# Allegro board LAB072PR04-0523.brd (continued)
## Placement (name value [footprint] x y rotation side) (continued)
T4928  PAD~D  [TPC12]  186.71 48.77 180 top
T4929  PAD~D  [TPC12]  185.77 49.77 180 top
T4930  PAD~D  [TPC12]  183.75 106.91 180 bottom
T4931  PAD~D  [TPC12]  152.21 98.78 0 top
T4932  PAD  [TPC12]  154.33 22.65 0 top
T4933  PAD  [TPC12]  154.2 85.73 0 top
T4934  PAD  [TPC12]  152.32 89.09 0 top
T4935  PAD  [TPC12]  153.18 88.13 0 top
T4939  PAD  [TPC12]  156.34 92.22 0 top
TL2  TAIMA_IH-115-F  [TAIMA_IH-115-F_24P]  187.84 80.38 90 bottom
U2301  -  [TPS22966DPUR_SON14_2X3]  179.07 52.27 0 top
U2302  -  [W25Q64FVSSIQ_SO8]  172.13 104.96 90 bottom
U2303  -  [74AUP1G07GW_TSSOP5]  134.92 58.62 270 top
U2304  -  [TPS22966DPUR_SON14_2X3]  179.99 63.37 90 top
U2412  ECE1117-HZH_QFN48_7X7~D  [ECE1117-HZH_QFN48_7X7]  82.36 13.48 0 top
UA1  -  [ALC3234-CG_MQFN48_6X6]  183.57 22.02 270 top
UC1  HASWELL-MCP-E-ULT_BGA1168  [HASWELL-MCP-E-ULT_BGA_1168P-T]  156.14 104.99 0 bottom
UC3  -  [MC74VHC1G08DFT2G_SC70-5]  176.92 84.95 180 top
UC4  -  [74CBTLV3126BQ_DHVQFN14_2P5X3]  88.52 89.92 90 top
UC5  -  [74AHC1G09GW_TSSOP5]  174.11 108.05 90 top
UC6  -  [74AUP1G07GW_TSSOP5]  124.39 113.08 180 top
UE4  ECE1099-FZG_QFN40_6X6~D  [ECE1099-FZG_QFN40_6X6]  94.62 19.58 270 top
UE5  -  [MEC5085-LZY_DQFN132_11X11]  146.55 9.72 0 top
UI2  -  [SY6288D20AAC_SOT23-5]  194.3 27.1 0 top
UI3  -  [SY6288D20AAC_SOT23-5]  195.25 35.86 90 top
UI4  -  [SY6288D20AAC_SOT23-5]  21.84 39.68 0 top
UL1  RTL8111GUS-CG_QFN32_4X4  [RTL8106E-CG_QFN32_4X4]  182.71 88.33 270 bottom
UL2  -  [SY6288C20AAC_SOT23-5]  182.69 82.73 270 top
UM1  -  [TPS22967DSGR_SON8_2X2]  176.35 50.87 90 top
US2  -  [PI3EQX6741STZDEX_TQFN20_4X4]  168.37 21.88 270 top
UV1  GM108-ES-S-A1_FCBGA595  [GM108-ES-S-A1_FCBGA_595P]  74.76 97.37 180 bottom
UV3  74AHCT1G125GW_SOT353-5~D  [74AHCT1G125GW_SOT353-5]  197.54 109.26 90 bottom
UV4  -  [AP2330W-7_SC59-3]  199.77 112.96 270 bottom
UV5  74AHCT1G125GW_SOT353-5~D  [74AHCT1G125GW_SOT353-5]  195.38 112.75 90 bottom
UV6  -  [IT6513FN_QFN48_6X6]  191.13 109.89 270 bottom
UV14  -  [MC74VHC1G08DFT2G_SC70-5]  79.75 82.97 90 top
UV15  -  [TPS22966DPUR_SON14_2X3]  87.82 102.73 270 bottom
UV17  H5TC4G63AFR-11C_FBGA96  [H5TC4G63AFR-11C_FBGA_96P]  43.01 95.15 90 bottom
UV18  H5TC4G63AFR-11C_FBGA96  [H5TC4G63AFR-11C_FBGA_96P]  43.01 101.55 270 top
UV19  H5TC4G63AFR-11C_FBGA96  [H5TC4G63AFR-11C_FBGA_96P]  43.01 81.74 270 top
UV20  H5TC4G63AFR-11C_FBGA96  [H5TC4G63AFR-11C_FBGA_96P]  43.01 75.34 90 bottom
UX1  -  [SY6288C20AAC_SOT23-5]  12.12 86.14 180 top
UX3  -  [SY6288C20AAC_SOT23-5]  14.64 100.71 0 top
YC1  32.768KHZ_12.5PF_9H03220008  [Y_9H03220008_2P]  159.29 76 180 top
YC2  24MHZ_12PF_X3G024000DC1H  [Y_X3G024000DC1H_4P]  136.79 112.65 180 bottom
YE1  32.768KHZ_9PF_Q13FC135000040  [Y_Q13FC135000040_2P]  140.01 10.19 270 top
YL2  25MHZ_10PF_7V25000014  [Y_7V25000014_4P]  184.34 94.38 180 bottom
YV1  27MHZ_12PF_X1E000021042600  [Y_X1E000021042600_4P]  75.79 106.52 0 bottom
YV3  27MHZ_12PF_X1E000021042600  [Y_X1E000021042600_4P]  182.9 113.16 180 bottom

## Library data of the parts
C7 C39-C45 C60 C66 C72 C74 C78 C82 C2305 C2306 C2308 C2309 C2311-C2318 C2322-C2325 C2328 C2329 C5259 C5261-C5263 CA55 CA57 CA59 CA61-CA64 CA67 CA68 CA71 CA74 CA77 CE4 CE42 CE45 CI40 CI43 CI44 CI49 CL43-CL45 CM4 CM6 CV15 CV16 CV24 CV32 CV33 CV36 CV39 CV42 CV43 CV46 CV47 CV65 CV112 CV130 CV135 CV136 CV158-CV160 CV164 CV340 CV361 CX5 CX22 PC103 PC106 PC312 PC313 PC520 PC525 PC528 PC605 PC614 PC617 PC625 PC700 PC723-PC725 PC745 PC751 PC752 PC924 PC925 PC928 PC930 PC938-PC941 PC952 PC953 PC1004 PC1006 = C_0603
C35-C38 C50-C58 C61-C64 C67-C69 C71 C73 C76 C77 C80 C81 C83 C85 C87 C88 C1160 C1313 C2326 C2327 C5212 C5254-C5256 C5291-C5293 CA21 CA26 CA32 CA38-CA40 CA54 CA56 CA58 CA60 CA65 CA69 CA75 CA76 CC14-CC16 CC41 CC42 CE3 CE10 CE13 CE14 CE17 CE21 CE38-CE41 CE43 CE44 CE46-CE55 CE58-CE66 CE68-CE70 CI2 CI9 CI15 CI26 CI46-CI48 CI50 CL20-CL22 CL24-CL26 CL30 CL31 CL34-CL37 CL39 CL41 CL42 CM3 CM5 CM7 CM8 CS5 CS6 CS27-CS29 CV30 CV34 CV35 CV40 CV45 CV48-CV64 CV68 CV129 CV131-CV134 CV139-CV143 CV151 CV161 CV163 CV165 CV168 CV170 CV172-CV174 CV178-CV181 CV183 CV184 CV186 CV187 CV196-CV199 CV203-CV205 CV208-CV211 CV215-CV218 CV326 CV334-CV339 CV341 CV343-CV345 CV351-CV360 CX2 CX4 CX6 CX10-CX21 CX23-CX31 CX50 CZ49-CZ51 PC2 PC3 PC9-PC11 PC16 PC17 PC104 PC108 PC202 PC210 PC521-PC523 PC526 PC527 PC529-PC531 PC541 PC545 PC546 PC548 PC600-PC602 PC606-PC608 PC612 PC615 PC616 PC618 PC619 PC622 PC626 PC746 PC747 PC750 PC926 PC927 PC929 PC931 PC1000 PC1001 PC1005 PC1009 = C_0402
C59 C65 C70 C84 C86 CL33 = C_1206
C2307 C2310 CS7 CX3 CX7 CX8 CX49 CX51 PC18 PC112 PC206 PC311 PC524 PC532 PC603 PC604 PC620 PC621 PC627 PC730-PC732 PC734 PC748 PC905-PC912 PC918-PC921 PC932-PC937 PC942 PC949-PC951 PC1002 PC1003 = C_0805
C4311-C4314 C4321 C4322 CM1 CM2 CS30-CS37 CV342 CV346-CV350 = C_0402: signal model: C_0402_C_0402
CA22-CA25 CA29-CA31 CA33 CA51 = C_0402: room: CODEC
CA53 = C_0603: room: CODEC
CC1-CC5 CC8 CC11 CC13 CC17 CC27-CC29 CC31 CC33-CC35 PC207 = C_0402: room: CPU
CC6 CC7 CC9 CC10 = C_0402: room: SPI
CC18-CC25 CV188-CV195 = C_0402: signal model: C_0402_0.22U_0402_16V7K
CC26 = C_0603: room: CPU
CC32 CC40 = C_0402: signal model: C_0402_C_0402; room: CPU
CD1-CD11 CD21-CD27 CD30-CD42 CD52-CD57 CD60 CD61 CD64 = C_0402: room: MEMORY
CD12-CD14 CD16-CD20 CD28 CD29 CD43-CD50 CD58 CD59 CD62 = C_0603: room: MEMORY
CD15 CD51 = C_D3: room: MEMORY
CE24 = C_0402: room: KBC
CI1 CI8 = C_1206: room: USB
CI3 CI4 CI10 CI11 CI13 CI17 = C_0402: room: USB
CI6 CI12 = C_0603: room: USB
CL15 = C_0402: room: LAN
CL19 = C_0402: room: HDMI
CMOS1 = SHORTPADS: User Part Number: PART#; room: CPU
D1 = RB751S40T1G_SOD523-2
DA8 DC1 DV1 DV2 DV7 = BAT54CW_SOT323-3
DA10 DA13 DX2-DX4 = AZ5125-02SPR7G_SOT23-3
DA12 DA14 = ESD207-B1-02EL_TSLP-2-19-2
DE1 = AZ5125-02SPR7G_SOT23-3: room: FAN
DE2 PD3 = AZ5125-01HPR7G_SOD523-2
DE3 DS1 DV5 DV6 = PJDLC05C_SOT23-3
DI1 DI4 = IP4292CZ10-TBR_XSON10_2P5X1: room: USB
DI2 DI5 = PJDLC05C_SOT23-3: room: USB
DV3 = RB751V-40_SOD323-2
F1 = F_KMC3S050RY
FD1-FD4 = FIDUCIAL_C40M80
FX1 = F_1206L150THWR
H1 = H_2P3: room: LED
H2 = H_2P8X3P1N: room: LED
H3 H4 H8 H11 H17 H19 = H_2P8: room: LED
H5 = H_6P6: room: LED
H6 = H_3P5: room: LED
H7 = H_3P2X3P5: room: LED
H9 = H_3P2X3P5
H10 = H_3P2
H12 = H_2P3N: room: LED
H14 = H_6P0: room: LED
H15 = H_3P2: room: LED
H20 H21 = H_1P1N
H22-H24 = H_3P3
JBATT = ALLTO_C144LS-109A9-L_9P-T
JCRT = C-K_80443A-5K1-152_15P
JDCIN = ACES_50299-00501-003_5P
JDEG JLPDE = ACES_87153-10411_10P
JDIMM1 = FOX_AS0A621-U4R6-7H_204P: room: CPU
JDIMM2 = FOX_AS0A621-U4S6-7H_204P: room: CPU
JEDP = ACES_50398-04041-001_40P
JFAN = ACES_50279-0040N-001_4P
JFP = ACES_51524-0060N-001_6P
JHDD = ACES_50208-01001-001_10P
JHDMI = CONCR_099ATAC19NBLCNF_19P
JHP = SINGA_2SJ3080-001111F_6P
JIO = ACES_51524-0160N-001_16P
JKB = ACES_51510-0304N-P01_30P
JKBBL = ACES_50524-00401-P01_4P
JLAN = J-L_TNBNRAC80015008_8P
JLED JTP = ACES_51524-0080N-001_8P
JNGFF = LOTES_APCI0019-P009A_67P
JRTC = ACES_50271-0020N-001_2P
JSPK = ACES_50278-00401-001_4P
JTAG1 = SHORTPADS: User Part Number: PART#
JUSB1 JUSB2 = TAITW_PUBAU6-09FLBS1NN4H0_9P: room: USB
JXDP = SAMTE_BSH-030-01-L-D-A_60P
L1-L5 = MURAT_LQM2MPN2R2NG0L_2P
L12 LX6 LX7 = MURAT_DLW21HN900HQ2L_4P: signal model: KC_WCM-2012HS-900T_4P_KC_WCM-2012HS-900T_4P
L18 = CHILI_NLC252018T-2R2J-N_2P
LA1 RA1121-RA1124 = MURAT_BLM15BB221SN1D_2P
LA8 LA9 = MURAT_BLM15BB221SN1D_2P: room: CODEC
LA10 LA11 = MURAT_BLM15PX330SN1D_2P
LI1 LI3 LI4 LI6 = MURAT_DLW21SN670HQ2L_4P: room: USB
LI2 LI5 = MURAT_DLW21HN900HQ2L_4P: room: USB
LV8 = TAI-T_HCB1608KF-121T3_L0603_2P
LV10 LV26 = MURAT_BLM18PG300SN1D_2P
LV14 LV15 LV21 = MURAT_BLM15PD600SN1D_2P
LV16-LV18 = MURAT_BLM15BB470SN1D_2P
LV19 LV20 = MURAT_BLM15AG121SN1D_L0402_2P
LX1 = KC_FBMA-L11-201209-221LMA30_2P
LX2-LX5 = MURAT_DLW21HN900HQ2L_4P
LX8-LX10 = MURAT_DLW21SN670HQ2L_4P
PC1 = C_0402: room: P_DCIN
PC5 = C_0603: room: P_DCIN
PC100 PC105 PC109 PC111 PC200 PC204 PC209 PC301 PC302 = C_0603: room: ETY-ROOM
PC101 = C_APXK6R3ARA221MF451: room: ETY-ROOM
PC102 PC110 PC114 PC201 PC203 PC300 PC303 PC304 PC307 PC400 PC402 PC403 PC500 PC510 PC519 = C_0402: room: ETY-ROOM
PC107 = C_APXK6R3ARA221MF451
PC113 = C_0402: room: 3V5V
PC115 = C_0805: room: 3V5V
PC116 PC117 PC299 = C_D2-NPM
PC205 PC211 PC212 PC305 PC306 PC308-PC310 PC401 PC404 = C_0805: room: ETY-ROOM
PC208 = C_0402: room: ADP3209
PC214 = C_MP6VU330MC6
PC515 PC516 = C_EEEFZ1E101P-NPM: room: CPU_CORE
PC517 PC518 = C_0805: room: CPU_CORE
PC533 PC534 = C_D
PC610 PC613 PC623 PC1008 = C_D2
PC701-PC703 PC718 PC719 PC726-PC728 = C_0402: room: CHARGER
PC704-PC711 PC716 PC717 PC720 = C_0805: room: CHARGER
PC712 PC722 = C_0603: room: CHARGER
PC721 = C_0805: room: ADP3209
PC729 = C_0603: room: P_SELECTOR
PC901-PC904 PC913-PC917 PC922 PC923 = C_0805: room: CPU
PD1 PD2 = TVNST52302AB0_SOT523-3: room: ETY-ROOM
PD101 = TVNST52302AB0_SOT523-3
PD702 PD703 = SDMK0340L-7-F_SOD323-2
PH500 PH501 PR102 PR104-PR108 PR114 PR205 PR207 PR208 PR301 PR305 PR307 PR400-PR403 PR500 PR512 PR528 PR539 = R_0402: room: ETY-ROOM
PH600 PR3-PR5 PR9-PR11 PR13 PR110 PR115 PR204 PR304 PR309 PR310 PR525 PR533 PR537 PR543 PR545 PR549 PR551 PR558 PR600 PR602-PR604 PR607 PR608 PR610 PR611 PR614 PR615 PR617 PR620 PR621 PR624 PR706 PR729-PR732 PR737 PR739-PR741 PR1000 PR1002 PR1005-PR1007 R1 R2 R10 R11 R16 R159 R944 R990 R2313 R2318 R2329-R2345 R2347-R2353 R2356-R2359 R2363 R2484 R2495 R2517 R2518 R2521-R2528 RA10 RA19 RA53 RA55 RA56 RA79-RA84 RA130 RA165 RA166 RA1109 RA1112 RA1113 RA1120 RA1128-RA1130 RC5 RC6 RC9 RC12 RC13 RC24 RC27 RC28 RC32 RC36 RC39 RC48 RC51 RC56 RC58 RC60 RC64 RC71 RC75 RC80 RC84 RC90 RC92 RC95 RC101 RC105 RC108 RC109 RC111 RC114 RC117 RC129 RC134 RC135 RC153 RC183 RC191 RC362-RC366 RC368-RC374 RE13 RE14 RE24-RE26 RE31 RE33 RE35 RE38 RE39 RE45 RE48 RE50 RE55-RE57 RE61 RE63-RE67 RE69 RE70 RE72 RE74-RE82 RE87 RE89 RE90 RE274 RE278-RE280 RL27 RL30 RL31 RL33 RL41 RM8 RN5 RS8 RS19 RS21 RS22 RS24 RS25 RS30 RS32 RS33 RS35 RS36 RS38 RS40-RS43 RV18 RV20 RV23-RV26 RV30-RV49 RV51 RV59 RV92-RV99 RV103 RV104 RV107 RV108 RV110 RV112 RV114 RV117-RV119 RV122-RV130 RV132 RV139 RV140 RV142-RV157 RV159-RV162 RV169-RV171 RV185 RV187-RV193 RV195 RV196 RV208 RV210 RV252 RV253 RV510-RV520 RX2 RX3 RX9 RX12 RX13 RX16 RX17 RX21 RX22 RX26 RX29-RX31 = R_0402
PJP12 PJP14 PJP15 PJP30 PJP31 PJP203 PJP701 = JUMP_43X39
PJP13 PJP400 PJP401 PJP510-PJP513 = JUMP_43X79
PJP100 PJP101 PJP300 = JUMP_43X118: room: ETY-ROOM
PJP103 PJP200 PJP201 PJP1000 = JUMP_43X118
PL1 PL2 PL4 = TAI-T_HCB2012KF-121T50_2P: room: P_DCIN
PL3 = MURAT_BLM15AG102SN1D_2P: room: P_DCIN
PL5-PL8 PL103 PL201 PL302 PL504 PL600 PL603 PL1000 = TAI-T_HCB2012KF-121T50_2P
PL100 PL101 PL200 = L_7X7X3_M_2P: room: ETY-ROOM
PL102 = TAI-T_HCB2012KF-121T50_2P: room: VDDCI
PL301 = L_5X5X3_M_2P: room: ETY-ROOM
PL501 = TAI-T_HCB2012KF-121T50_2P: room: CPU_CORE
PL502 = CYNTE_PCMB104T-R15MS0R485_4P
PL601 PL602 = PANAS_ETQP3W2R2WFN_2P
PL700 = L_5X5X3_M_2P
PL701 = L_10X10X4_M_2P: room: ETY-ROOM
PL1001 = L_7X7X3_M_2P
PQ1 = FDV301N_NL_SOT23-3: room: P_DCIN
PQ2 = MMST3904-7-F_SOT323-3: room: P_DCIN
PQ3 = 2N7002KDWH_SOT363-6
PQ101 PQ103 = MDV1528URH_PDFN33-8-5: room: ETY-ROOM
PQ102 = FDMC7692S_MLP8-5: room: ETY-ROOM
PQ104 PQ201 = FDMC7692S_MLP8-5
PQ200 = MDV1528URH_PDFN33-8-5
PQ501 = CSD87351Q5D_SON8-7
PQ600 PQ602 = MDU1516URH_POWERDFN56-8-5
PQ601 PQ603 = MDU1511RH_POWERDFN56-8-5
PQ701 = MDU1516URH_POWERDFN56-8-5: room: ETY-ROOM
PQ702 = MDS1525URH_SO8: room: ETY-ROOM
PQ703 = AO4407AL_SO8
PQ704 = SIR472DP-T1-GE3_POWERPAK8-5
PQ705 = SIRA06DP-T1-GE_POWERPAKSO-8-5
PQ708 = DCX124EK-7-F_SC74R-6
PQ709 = DMN65D8LW-7_SOT323-3
PQ1000 = SIS412DN-T1-GE3_POWERPAK8-5
PQ1001 = MDV1526URH_PDFN33-8-5
PR2 PR6-PR8 = R_0402: room: P_DCIN
PR12 PR613 PR622 PR1004 = R_1206
PR16 RM7 = R_0805
PR100 PR101 PR201 PR202 = R0402_0OHM: room: ETY-ROOM
PR103 PR111 PR206 PR303 PR536 = R_0603: room: ETY-ROOM
PR109 PR519 = R_0402: room: CPU_CORE
PR112 PR113 PR203 PR302 PR534 = R_1206: room: ETY-ROOM
PR200 = R_0603: room: CPU_CORE
PR300 PR601 PR605 PR612 PR616 PR719 PR721 PR738 PR1003 R248 R250 R251 R265 R416 R2355 R2360 R2451 R2532 RC37 RC40-RC47 RC49 RC52-RC55 RC57 RC59 RC78 RC97 RC107 RC367 RD1 RD8 RE32 RE58 RE62 RE275 RM5 RM6 RS39 RV163 RV164 RV215 RX32-RX37 = R0402_0OHM
PR306 PR308 = R_0402: room: 1P5V
PR504 PR507 PR521 PR535 = R_0402: room: GPU_CORE
PR505 PR506 PR508 PR510 PR511 = R0402_0OHM: room: GPU_CORE
PR513 PR538 PR606 PR609 PR618 PR619 PR623 PR1001 R245 R2314 RL39 RL40 RX28 = R_0603
PR702 = R_1206_4P-D
PR704 PR713 PR715 PR725 = R_0402: room: CHARGER
PR705 PR714 PR716-PR718 PR720 PR728 = R0402_0OHM: room: CHARGER
PR708 PR711 = R_1206: room: CHARGER
PR710 = R_1206_4P-D: room: CHARGER
PR712 = R_0603: room: 3V5V
PR723 = R_0603: room: CHARGER
PRP1 RP37 RP39 RP40 RP43 RP44 RP48 RP51-RP53 RP55 RP58-RP60 RPE3 RPE5-RPE7 RPE9 RPE10 RPV3 = RP_0804_8P4R
PU100 = TPS51285BRUKR_QFN20_3X3: room: ETY-ROOM
PU200 = G5616ARZ1U_TQFN20_3X3: room: ETY-ROOM
PU300 = SY8206DQNC_QFN10_3X3: room: ETY-ROOM
PU400 = APL5930KAI-TRG_SO8: room: ETY-ROOM
PU501 = ISL95813HRZ-T_QFN20_3X4: room: ETY-ROOM
PU600 = RT8813AGQW_WQFN24_4X4
PU700 = BQ24777RUYR_WQFN28_4X4
PU1000 = TPS51212DSCR_SON10_3X3
Q8-Q10 Q2307 Q2416 QX3 = 2N7002K_SOT23-3
Q327 QA7 QD2 QE11 QV5 QV78 QV88 QX1 = L2N7002WT1G_SC-70-3
Q330 QX5 = AO3419L_SOT23-3
QA6 QV14 QV89 QX4 = DMN66D0LDW-7_SOT363-6
QC1 = DMN66D0LDW-7_SOT363-6: room: CPU
QE3 QE7-QE10 QE12 = MMST3904-7-F_SOT323-3
QX2 = SI3457CDV-T1-GE3_TSOP6
R246 RA1110 RA1111 RA1114-RA1117 RA1125 RV214 = R0603_0OHM
R252-R256 = R_0402: room: DOCK
R257 = R0402_0OHM: room: DOCK
R264 = R0603_0OHM: room: DOCK
R267 = R0805_0OHM: room: DOCK
RA5 RA6 = R_0402: room: CODEC
RA8 = R0402_0OHM: room: CODEC
RC1 RC2 RC4 RC7 RC8 RC10 RC14-RC23 RC25 RC34 RC63 RC65-RC70 RC72 RC87 RC89 RC91 RC98 RC102 RC103 RC106 RC116 RC118-RC121 RC130-RC133 = R_0402: room: CPU
RC29 = R_0402: room: FLASH ROM
RC38 RC50 = R0402_0OHM: room: SPI
RC62 = R_0402: room: SPI
RC81 RC127 = R0402_0OHM: room: CPU
RC126 = R0603_0OHM: room: CPU
RD3 RD6 RD7 RD12 RD13 = R_0402: room: MEMORY
RD4 RD5 RD10 = R0402_0OHM: room: MEMORY
RL19 RL20 = R_0603: room: LOM
RS26 RS27 RX23 RX24 = R_0402: signal model: R_0402_R_0402
SW1 = SW_SMT1-05-A_4P: room: CPU
SW3 = SW_SSAL120100_3P
T27 T32 T38-T51 T53 T55 T56 T58 T59 T87 T94-T96 T99-T102 T110-T121 T124 T126-T159 T161 T163-T177 T179-T184 T3861 T3862 T4927-T4935 T4939 = TPC12
T97 T98 = TPC12: room: SIO
TL2 = TAIMA_IH-115-F_24P
U2301 U2304 UV15 = TPS22966DPUR_SON14_2X3
U2302 = W25Q64FVSSIQ_SO8
U2303 UC6 = 74AUP1G07GW_TSSOP5
U2412 = ECE1117-HZH_QFN48_7X7
UA1 = ALC3234-CG_MQFN48_6X6: room: CODEC
UC1 = HASWELL-MCP-E-ULT_BGA_1168P-T: room: CPU
UC3 = MC74VHC1G08DFT2G_SC70-5: room: SPI
UC4 = 74CBTLV3126BQ_DHVQFN14_2P5X3: room: CPU
UC5 = 74AHC1G09GW_TSSOP5
UE4 = ECE1099-FZG_QFN40_6X6
UE5 = MEC5085-LZY_DQFN132_11X11
UI2 UI3 = SY6288D20AAC_SOT23-5: room: USB
UI4 = SY6288D20AAC_SOT23-5
UL1 = RTL8106E-CG_QFN32_4X4: room: LAN
UL2 = SY6288C20AAC_SOT23-5: room: LAN
UM1 = TPS22967DSGR_SON8_2X2
US2 = PI3EQX6741STZDEX_TQFN20_4X4
UV1 = GM108-ES-S-A1_FCBGA_595P
UV3 UV5 = 74AHCT1G125GW_SOT353-5
UV4 = AP2330W-7_SC59-3
UV6 = IT6513FN_QFN48_6X6
UV14 = MC74VHC1G08DFT2G_SC70-5
UV17-UV20 = H5TC4G63AFR-11C_FBGA_96P
UX1 UX3 = SY6288C20AAC_SOT23-5
YC1 = Y_9H03220008_2P: room: CPU
YC2 = Y_X3G024000DC1H_4P: room: CPU
YE1 = Y_Q13FC135000040_2P
YL2 = Y_7V25000014_4P
YV1 YV3 = Y_X1E000021042600_4P

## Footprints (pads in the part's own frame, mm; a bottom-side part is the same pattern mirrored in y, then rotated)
2N7002K_SOT23-3
  oval 1.016x1.524 smd: 1(0,0) 2(0.965,2.083) 3(-0.965,2.083)
2N7002KDWH_SOT363-6
  oval 0.356x0.889 smd: 1(0,0) 2(0.65,0) 3(1.3,0) 4(1.3,1.6) 5(0.65,1.6) 6(0,1.6)
74AHC1G09GW_TSSOP5
  oval 0.381x1.346 smd: 1(0,0) 2(0.65,0) 3(1.3,0) 4(1.3,1.79) 5(0,1.79)
74AHCT1G125GW_SOT353-5
  oval 0.381x0.838 smd: 1(0,0) 2(0.65,0) 3(1.3,0) 4(1.3,1.79) 5(0,1.79)
74AUP1G07GW_TSSOP5
  oval 0.381x1.346 smd: 1(0,0) 2(0.65,0) 3(1.3,0) 4(1.3,1.79) 5(0,1.79)
74CBTLV3126BQ_DHVQFN14_2P5X3
  oval 1.041x0.254 smd: 1(0,0) 7(2.95,0) 8(2.95,0.5) 14(0,0.5)
  oval 0.254x1.041 smd: 2(0.475,-0.975) 3(0.975,-0.975) 4(1.475,-0.975) 5(1.975,-0.975) 6(2.475,-0.975) 9(2.475,1.475) 10(1.975,1.475) 11(1.475,1.475) 12(0.975,1.475) 13(0.475,1.475)
  rect 1.499x0.991 smd: 15(1.475,0.25)
ACES_50208-01001-001_10P
  oval 0.508x0.991 smd: 1(0,0) 2(0.8,0) 3(1.6,0) 4(2.4,0) 5(3.2,0) 6(4,0) 7(4.8,0) 8(5.6,0) 9(6.4,0) 10(7.2,0)
  rect 1.194x1.702 smd: 11(-1.3,-1.95) 12(8.5,-1.95)
ACES_50271-0020N-001_2P
  oval 0.787x1.6 smd: 1(0,0) 2(1.25,0)
  rect 2.108x2.997 smd: 3(3.8,-2.9) 4(-2.55,-2.9)
ACES_50278-00401-001_4P
  oval 0.787x1.905 smd: 1(0,0) 2(1.25,0) 3(2.5,0) 4(3.75,0)
  rect 1.295x3.353 smd: 5(-2.85,-4.925) 6(6.6,-4.925)
ACES_50279-0040N-001_4P
  oval 0.787x1.905 smd: 1(0,0) 2(1.25,0) 3(2.5,0) 4(3.75,0)
  rect 1.295x3.353 smd: 5(6.6,-4.925) 6(-2.85,-4.925)
ACES_50299-00501-003_5P
  round 1.803 hole 1.803 unplated: (-0.2,5.2) (8.2,5.2)
  oval 0.889x2.388 smd: 1(0,0) 2(2,0) 3(4,0) 4(6,0) 5(8,0)
ACES_50398-04041-001_40P
  oval 0.254x1.295 smd: 1(0,0) 2(0.5,0) 3(1,0) 4(1.5,0) 5(2,0) 6(2.5,0) 7(3,0) 8(3.5,0) 9(4,0) 10(4.5,0) 11(5,0) 12(5.5,0) 13(6,0) 14(6.5,0) 15(7,0) 16(7.5,0) 17(8,0) 18(8.5,0) 19(9,0) 20(9.5,0) 21(10,0) 22(10.5,0) 23(11,0) 24(11.5,0) 25(12,0) 26(12.5,0) 27(13,0) 28(13.5,0) 29(14,0) 30(14.5,0) 31(15,0) 32(15.5,0) 33(16,0) 34(16.5,0) 35(17,0) 36(17.5,0) 37(18,0) 38(18.5,0) 39(19,0) 40(19.5,0)
  rect 1.194x3.2 smd: 41(-2.4,1.95) 45(21.9,1.95)
  rect 2.311x1.295 smd: 42(0.85,3.9) 43(9.75,3.9) 44(18.65,3.9)
ACES_50524-00401-P01_4P
  oval 0.305x1.295 smd: 1(0,0) 2(1,0) 3(2,0) 4(3,0)
  rect 1.803x2.21 smd: 5(5.65,-5.65) 6(-2.65,-5.65)
ACES_51510-0304N-P01_30P
  oval 0.305x1.295 smd: 1(0,0) 2(0.8,0) 3(1.6,0) 4(2.4,0) 5(3.2,0) 6(4,0) 7(4.8,0) 8(5.6,0) 9(6.4,0) 10(7.2,0) 11(8,0) 12(8.8,0) 13(9.6,0) 14(10.4,0) 15(11.2,0) 16(12,0) 17(12.8,0) 18(13.6,0) 19(14.4,0) 20(15.2,0) 21(16,0) 22(16.8,0) 23(17.6,0) 24(18.4,0) 25(19.2,0) 26(20,0) 27(20.8,0) 28(21.6,0) 29(22.4,0) 30(23.2,0)
  rect 1.803x2.21 smd: 31(25.55,-5.65) 32(-2.35,-5.65)
ACES_51524-0060N-001_6P
  oval 0.61x1.295 smd: 1(0,0) 2(1,0) 3(2,0) 4(3,0) 5(4,0) 6(5,0)
  rect 2.159x2.21 smd: 7(-2.825,-3.05) 8(7.825,-3.05)
ACES_51524-0080N-001_8P
  oval 0.61x1.295 smd: 1(0,0) 2(1,0) 3(2,0) 4(3,0) 5(4,0) 6(5,0) 7(6,0) 8(7,0)
  rect 2.489x2.21 smd: 9(10,-3.05) 10(-3,-3.05)
ACES_51524-0160N-001_16P
  oval 0.61x1.295 smd: 1(0,0) 2(1,0) 3(2,0) 4(3,0) 5(4,0) 6(5,0) 7(6,0) 8(7,0) 9(8,0) 10(9,0) 11(10,0) 12(11,0) 13(12,0) 14(13,0) 15(14,0) 16(15,0)
  rect 2.159x2.21 smd: 17(-2.825,-3.05) 18(17.825,-3.05)
ACES_87153-10411_10P
  oval 0.61x1.499 smd: 1(0,0) 2(0.5,3) 3(1,0) 4(1.5,3) 5(2,0) 6(2.5,3) 7(3,0) 8(3.5,3) 9(4,0) 10(4.5,3)
  rect 0.787x1.499 smd: 11(5.5,3) 12(5.5,0) 13(-1,0) 14(-1,3)
ALC3234-CG_MQFN48_6X6
  oval 0.203x0.889 smd: 1(0,0) 2(0.4,0) 3(0.8,0) 4(1.2,0) 5(1.6,0) 6(2,0) 7(2.4,0) 8(2.8,0) 9(3.2,0) 10(3.6,0) 11(4,0) 12(4.4,0) 25(4.4,6.1) 26(4,6.1) 27(3.6,6.1) 28(3.2,6.1) 29(2.8,6.1) 30(2.4,6.1) 31(2,6.1) 32(1.6,6.1) 33(1.2,6.1) 34(0.8,6.1) 35(0.4,6.1) 36(0,6.1)
  oval 0.889x0.203 smd: 13(5.25,0.85) 14(5.25,1.25) 15(5.25,1.65) 16(5.25,2.05) 17(5.25,2.45) 18(5.25,2.85) 19(5.25,3.25) 20(5.25,3.65) 21(5.25,4.05) 22(5.25,4.45) 23(5.25,4.85) 24(5.25,5.25) 37(-0.85,5.25) 38(-0.85,4.85) 39(-0.85,4.45) 40(-0.85,4.05) 41(-0.85,3.65) 42(-0.85,3.25) 43(-0.85,2.85) 44(-0.85,2.45) 45(-0.85,2.05) 46(-0.85,1.65) 47(-0.85,1.25) 48(-0.85,0.85)
  rect 4.394x4.394 smd: 49(2.2,3.05)
ALLTO_C144LS-109A9-L_9P-T
  round 1.803 hole 1.194: 1(0,0) 2(2,0) 3(4,0) 4(6,0) 5(8,0) 6(10,0) 7(12,0) 8(14,0) 9(16,0)
  oval 1.6x3.404 hole 0.991x2.794: 10(19.125,0.25) 11(-3.125,0.25)
AO3419L_SOT23-3
  oval 1.016x1.524 smd: 1(0,0) 2(0.965,2.083) 3(-0.965,2.083)
AO4407AL_SO8
  oval 0.635x1.854 smd: 1(0,0) 2(1.27,0) 3(2.54,0) 4(3.81,0) 5(3.81,5.165) 6(2.54,5.165) 7(1.27,5.165) 8(0,5.165)
AP2330W-7_SC59-3
  oval 0.787x0.991 smd: 1(0,0) 2(-0.95,-2.4) 3(0.95,-2.4)
APL5930KAI-TRG_SO8
  oval 0.635x1.854 smd: 1(0,0) 2(1.27,0) 3(2.54,0) 4(3.81,0) 5(3.81,5.165) 6(2.54,5.165) 7(1.27,5.165) 8(0,5.165)
  rect 2.87x2.489 smd: 9(1.905,2.582)
AZ5125-01HPR7G_SOD523-2
  rect 0.61x0.787 smd: 1(0,0) 2(1.5,0)
AZ5125-02SPR7G_SOT23-3
  oval 1.016x1.524 smd: 1(0,0) 2(0.965,2.083) 3(-0.965,2.083)
BAT54CW_SOT323-3
  oval 0.61x0.559 smd: 1(0,0) 2(-0.65,-1.85) 3(0.65,-1.85)
BQ24777RUYR_WQFN28_4X4
  oval 0.889x0.203 smd: 1(0,0) 2(0,-0.4) 3(0,-0.8) 4(0,-1.2) 5(0,-1.6) 6(0,-2) 7(0,-2.4) 15(4.1,-2.4) 16(4.1,-2) 17(4.1,-1.6) 18(4.1,-1.2) 19(4.1,-0.8) 20(4.1,-0.4) 21(4.1,0)
  oval 0.203x0.889 smd: 8(0.85,-3.25) 9(1.25,-3.25) 10(1.65,-3.25) 11(2.05,-3.25) 12(2.45,-3.25) 13(2.85,-3.25) 14(3.25,-3.25) 22(3.25,0.85) 23(2.85,0.85) 24(2.45,0.85) 25(2.05,0.85) 26(1.65,0.85) 27(1.25,0.85) 28(0.85,0.85)
  rect 2.591x2.591 smd: 29(2.05,-1.2)
C-K_80443A-5K1-152_15P
  round 0.965 hole 0.711: 1(0,0) 2(2.29,0) 3(4.58,0) 4(6.87,0) 5(9.16,0) 6(-1.145,0) 7(1.145,0) 8(3.435,0) 9(5.725,0) 10(8.015,0) 11(0,1.4) 12(2.29,1.4) 13(4.58,1.4) 14(6.87,1.4) 15(9.16,1.4)
  oval 1.473x3.251 hole 0.711x2.489: 16(-5.47,-0.1) 17(14.63,-0.1)
C_0402
  rect 0.508x0.559 smd: 1(0,0) 2(0.914,0)
C_0603
  rect 0.635x0.889 smd: 1(0,0) 2(1.397,0)
C_0805
  rect 0.813x1.397 smd: 1(0,0) 2(1.702,0)
C_1206
  rect 1.016x1.651 smd: 1(0,0) 2(2.667,0)
C_APXK6R3ARA221MF451
  oval 3.15x1.6 smd: 1(0,0) 2(5.05,0)
C_D
  rect 2.388x2.896 smd: 1(0,0) 2(6.1,0)
C_D2
  rect 2.388x2.794 smd: 1(0,0) 2(6.4,0)
C_D2-NPM
  rect 2.388x2.794 smd: 1(0,0) 2(6.4,0)
C_D3
  rect 2.388x2.794 smd: 1(0,0) 2(6.4,0)
C_EEEFZ1E101P-NPM
  oval 3.2x1.6 smd: 1(0,0) 2(5,0)
C_MP6VU330MC6
  oval 3.505x1.6 smd: 1(0,0) 2(5.6,0)
CHILI_NLC252018T-2R2J-N_2P
  rect 1.016x2.54 smd: 1(0,0) 2(2.29,0)
CONCR_099ATAC19NBLCNF_19P
  round 0.813 hole 0.559: 1(0,0) 2(0.5,1.55) 3(1,0) 4(1.5,1.55) 5(2,0) 6(2.5,1.55) 7(3,0) 8(3.5,1.55) 9(4,0) 10(4.5,1.55) 11(5,0) 12(5.5,1.55) 13(6,0) 14(6.5,1.55) 15(7,0) 16(7.5,1.55) 17(8,0) 18(8.5,1.55) 19(9,0)
  oval 1.499x2.21 hole 0.889x1.6: 20(-2.75,1.7) 21(-4.65,-6.5) 22(11.75,1.7) 23(13.65,-7.75)
CSD87351Q5D_SON8-7
  oval 1.93x0.838 smd: 1(0,0)
  oval 0.66x0.838 smd: 2(1.905,0) 3(3.175,0) 4(3.175,5.39) 5(1.905,5.39) 6(0.635,5.39) 7(-0.635,5.39)
  custom 0.87x0.87 smd: 8(1.27,2.695)
CYNTE_PCMB104T-R15MS0R485_4P
  custom 0.876x0.876 smd: 1(0,0) 4(13.411,0)
  rect 2.032x0.508 smd: 2(2.489,0) 3(10.922,0)
DCX124EK-7-F_SC74R-6
  oval 0.559x0.787 smd: 1(0,0) 2(-0.95,0) 3(-1.9,0) 4(-1.9,2.4) 5(-0.95,2.4) 6(0,2.4)
DMN65D8LW-7_SOT323-3
  oval 0.711x0.889 smd: 1(0,0) 2(-0.65,-1.9) 3(0.65,-1.9)
DMN66D0LDW-7_SOT363-6
  oval 0.432x0.61 smd: 1(0,0) 2(0.65,0) 3(1.3,0) 4(1.3,1.9) 5(0.65,1.9) 6(0,1.9)
ECE1099-FZG_QFN40_6X6
  oval 0.254x1.041 smd: 1(0,0) 2(0.5,0) 3(1,0) 4(1.5,0) 5(2,0) 6(2.5,0) 7(3,0) 8(3.5,0) 9(4,0) 10(4.5,0) 21(4.5,5.95) 22(4,5.95) 23(3.5,5.95) 24(3,5.95) 25(2.5,5.95) 26(2,5.95) 27(1.5,5.95) 28(1,5.95) 29(0.5,5.95) 30(0,5.95)
  oval 1.041x0.254 smd: 11(5.225,0.725) 12(5.225,1.225) 13(5.225,1.725) 14(5.225,2.225) 15(5.225,2.725) 16(5.225,3.225) 17(5.225,3.725) 18(5.225,4.225) 19(5.225,4.725) 20(5.225,5.225) 31(-0.725,5.225) 32(-0.725,4.725) 33(-0.725,4.225) 34(-0.725,3.725) 35(-0.725,3.225) 36(-0.725,2.725) 37(-0.725,2.225) 38(-0.725,1.725) 39(-0.725,1.225) 40(-0.725,0.725)
  rect 4.089x4.089 smd: 41(2.25,2.975)
ECE1117-HZH_QFN48_7X7
  oval 0.254x0.889 smd: 1(0,0) 2(0.5,0) 3(1,0) 4(1.5,0) 5(2,0) 6(2.5,0) 7(3,0) 8(3.5,0) 9(4,0) 10(4.5,0) 11(5,0) 12(5.5,0) 25(5.5,7.1) 26(5,7.1) 27(4.5,7.1) 28(4,7.1) 29(3.5,7.1) 30(3,7.1) 31(2.5,7.1) 32(2,7.1) 33(1.5,7.1) 34(1,7.1) 35(0.5,7.1) 36(0,7.1)
  oval 0.889x0.254 smd: 13(6.3,0.8) 14(6.3,1.3) 15(6.3,1.8) 16(6.3,2.3) 17(6.3,2.8) 18(6.3,3.3) 19(6.3,3.8) 20(6.3,4.3) 21(6.3,4.8) 22(6.3,5.3) 23(6.3,5.8) 24(6.3,6.3) 37(-0.8,6.3) 38(-0.8,5.8) 39(-0.8,5.3) 40(-0.8,4.8) 41(-0.8,4.3) 42(-0.8,3.8) 43(-0.8,3.3) 44(-0.8,2.8) 45(-0.8,2.3) 46(-0.8,1.8) 47(-0.8,1.3) 48(-0.8,0.8)
  rect 4.089x4.089 smd: 49(2.75,3.55)
ESD207-B1-02EL_TSLP-2-19-2
  rect 0.356x0.61 smd: 1(0,0) 2(0.65,0)
F_1206L150THWR
  rect 0.991x1.803 smd: 1(0,0) 2(2.8,0)
F_KMC3S050RY
  rect 0.991x1.905 smd: 1(0,0) 2(3,0)
FDMC7692S_MLP8-5
  oval 0.432x0.711 smd: 1(0,0) 2(0.65,0) 3(1.3,0) 4(1.95,0)
  custom 0.537x0.537 smd: 5(0.975,2.075)
FDV301N_NL_SOT23-3
  oval 1.016x1.524 smd: 1(0,0) 2(0.965,2.083) 3(-0.965,2.083)
FIDUCIAL_C40M80
  round 1.016 smd: 1(0,0)
FOX_AS0A621-U4R6-7H_204P
  round 1.092 hole 1.092 unplated: (-65.05,-4.1)
  round 1.6 hole 1.6 unplated: (1.75,-4.1)
  oval 0.356x2.007 smd: 1(0,0) 2(-0.3,-8.2) 3(-0.6,0) 4(-0.9,-8.2) 5(-1.2,0) 6(-1.5,-8.2) 7(-1.8,0) 8(-2.1,-8.2) 9(-2.4,0) 10(-2.7,-8.2) 11(-3,0) 12(-3.3,-8.2) 13(-3.6,0) 14(-3.9,-8.2) 15(-4.2,0) 16(-4.5,-8.2) 17(-4.8,0) 18(-5.1,-8.2) 19(-5.4,0) 20(-5.7,-8.2) 21(-6,0) 22(-6.3,-8.2) 23(-6.6,0) 24(-6.9,-8.2) 25(-7.2,0) 26(-7.5,-8.2) 27(-7.8,0) 28(-8.1,-8.2) 29(-8.4,0) 30(-8.7,-8.2) 31(-9,0) 32(-9.3,-8.2) 33(-9.6,0) 34(-9.9,-8.2) 35(-10.2,0) 36(-10.5,-8.2) 37(-10.8,0) 38(-11.1,-8.2) 39(-11.4,0) 40(-11.7,-8.2) 41(-12,0) 42(-12.3,-8.2) 43(-12.6,0) 44(-12.9,-8.2) 45(-13.2,0) 46(-13.5,-8.2) 47(-13.8,0) 48(-14.1,-8.2) 49(-14.4,0) 50(-14.7,-8.2) 51(-15,0) 52(-15.3,-8.2) 53(-15.6,0) 54(-15.9,-8.2) 55(-16.2,0) 56(-16.5,-8.2) 57(-16.8,0) 58(-17.1,-8.2) 59(-17.4,0) 60(-17.7,-8.2) 61(-18,0) 62(-18.3,-8.2) 63(-18.6,0) 64(-18.9,-8.2) 65(-19.2,0) 66(-19.5,-8.2) 67(-19.8,0) 68(-20.1,-8.2) 69(-20.4,0) 70(-20.7,-8.2) 71(-21,0) 72(-21.3,-8.2) 73(-24,0) 74(-24.3,-8.2) 75(-24.6,0) 76(-24.9,-8.2) 77(-25.2,0) 78(-25.5,-8.2) 79(-25.8,0) 80(-26.1,-8.2) 81(-26.4,0) 82(-26.7,-8.2) 83(-27,0) 84(-27.3,-8.2) 85(-27.6,0) 86(-27.9,-8.2) 87(-28.2,0) 88(-28.5,-8.2) 89(-28.8,0) 90(-29.1,-8.2) 91(-29.4,0) 92(-29.7,-8.2) 93(-30,0) 94(-30.3,-8.2) 95(-30.6,0) 96(-30.9,-8.2) 97(-31.2,0) 98(-31.5,-8.2) 99(-31.8,0) 100(-32.1,-8.2) 101(-32.4,0) 102(-32.7,-8.2) 103(-33,0) 104(-33.3,-8.2) 105(-33.6,0) 106(-33.9,-8.2) 107(-34.2,0) 108(-34.5,-8.2) 109(-34.8,0) 110(-35.1,-8.2) 111(-35.4,0) 112(-35.7,-8.2) 113(-36,0) 114(-36.3,-8.2) 115(-36.6,0) 116(-36.9,-8.2) 117(-37.2,0) 118(-37.5,-8.2) 119(-37.8,0) 120(-38.1,-8.2) 121(-38.4,0) 122(-38.7,-8.2) 123(-39,0) 124(-39.3,-8.2) 125(-39.6,0) 126(-39.9,-8.2) 127(-40.2,0) 128(-40.5,-8.2) 129(-40.8,0) 130(-41.1,-8.2) 131(-41.4,0) 132(-41.7,-8.2) 133(-42,0) 134(-42.3,-8.2) 135(-42.6,0) 136(-42.9,-8.2) 137(-43.2,0) 138(-43.5,-8.2) 139(-43.8,0) 140(-44.1,-8.2) 141(-44.4,0) 142(-44.7,-8.2) 143(-45,0) 144(-45.3,-8.2) 145(-45.6,0) 146(-45.9,-8.2) 147(-46.2,0) 148(-46.5,-8.2) 149(-46.8,0) 150(-47.1,-8.2) 151(-47.4,0) 152(-47.7,-8.2) 153(-48,0) 154(-48.3,-8.2) 155(-48.6,0) 156(-48.9,-8.2) 157(-49.2,0) 158(-49.5,-8.2) 159(-49.8,0) 160(-50.1,-8.2) 161(-50.4,0) 162(-50.7,-8.2) 163(-51,0) 164(-51.3,-8.2) 165(-51.6,0) 166(-51.9,-8.2) 167(-52.2,0) 168(-52.5,-8.2) 169(-52.8,0) 170(-53.1,-8.2) 171(-53.4,0) 172(-53.7,-8.2) 173(-54,0) 174(-54.3,-8.2) 175(-54.6,0) 176(-54.9,-8.2) 177(-55.2,0) 178(-55.5,-8.2) 179(-55.8,0) 180(-56.1,-8.2) 181(-56.4,0) 182(-56.7,-8.2) 183(-57,0) 184(-57.3,-8.2) 185(-57.6,0) 186(-57.9,-8.2) 187(-58.2,0) 188(-58.5,-8.2) 189(-58.8,0) 190(-59.1,-8.2) 191(-59.4,0) 192(-59.7,-8.2) 193(-60,0) 194(-60.3,-8.2) 195(-60.6,0) 196(-60.9,-8.2) 197(-61.2,0) 198(-61.5,-8.2) 199(-61.8,0) 200(-62.1,-8.2) 201(-62.4,0) 202(-62.7,-8.2) 203(-63,0) 204(-63.3,-8.2)
  rect 3.505x4.597 smd: 205(-64.45,7.9) 206(1.15,7.9)
FOX_AS0A621-U4S6-7H_204P
  round 1.6 hole 1.6 unplated: (-1.75,4.1)
  round 1.092 hole 1.092 unplated: (65.05,4.1)
  oval 0.356x2.007 smd: 1(0,0) 2(0.3,8.2) 3(0.6,0) 4(0.9,8.2) 5(1.2,0) 6(1.5,8.2) 7(1.8,0) 8(2.1,8.2) 9(2.4,0) 10(2.7,8.2) 11(3,0) 12(3.3,8.2) 13(3.6,0) 14(3.9,8.2) 15(4.2,0) 16(4.5,8.2) 17(4.8,0) 18(5.1,8.2) 19(5.4,0) 20(5.7,8.2) 21(6,0) 22(6.3,8.2) 23(6.6,0) 24(6.9,8.2) 25(7.2,0) 26(7.5,8.2) 27(7.8,0) 28(8.1,8.2) 29(8.4,0) 30(8.7,8.2) 31(9,0) 32(9.3,8.2) 33(9.6,0) 34(9.9,8.2) 35(10.2,0) 36(10.5,8.2) 37(10.8,0) 38(11.1,8.2) 39(11.4,0) 40(11.7,8.2) 41(12,0) 42(12.3,8.2) 43(12.6,0) 44(12.9,8.2) 45(13.2,0) 46(13.5,8.2) 47(13.8,0) 48(14.1,8.2) 49(14.4,0) 50(14.7,8.2) 51(15,0) 52(15.3,8.2) 53(15.6,0) 54(15.9,8.2) 55(16.2,0) 56(16.5,8.2) 57(16.8,0) 58(17.1,8.2) 59(17.4,0) 60(17.7,8.2) 61(18,0) 62(18.3,8.2) 63(18.6,0) 64(18.9,8.2) 65(19.2,0) 66(19.5,8.2) 67(19.8,0) 68(20.1,8.2) 69(20.4,0) 70(20.7,8.2) 71(21,0) 72(21.3,8.2) 73(24,0) 74(24.3,8.2) 75(24.6,0) 76(24.9,8.2) 77(25.2,0) 78(25.5,8.2) 79(25.8,0) 80(26.1,8.2) 81(26.4,0) 82(26.7,8.2) 83(27,0) 84(27.3,8.2) 85(27.6,0) 86(27.9,8.2) 87(28.2,0) 88(28.5,8.2) 89(28.8,0) 90(29.1,8.2) 91(29.4,0) 92(29.7,8.2) 93(30,0) 94(30.3,8.2) 95(30.6,0) 96(30.9,8.2) 97(31.2,0) 98(31.5,8.2) 99(31.8,0) 100(32.1,8.2) 101(32.4,0) 102(32.7,8.2) 103(33,0) 104(33.3,8.2) 105(33.6,0) 106(33.9,8.2) 107(34.2,0) 108(34.5,8.2) 109(34.8,0) 110(35.1,8.2) 111(35.4,0) 112(35.7,8.2) 113(36,0) 114(36.3,8.2) 115(36.6,0) 116(36.9,8.2) 117(37.2,0) 118(37.5,8.2) 119(37.8,0) 120(38.1,8.2) 121(38.4,0) 122(38.7,8.2) 123(39,0) 124(39.3,8.2) 125(39.6,0) 126(39.9,8.2) 127(40.2,0) 128(40.5,8.2) 129(40.8,0) 130(41.1,8.2) 131(41.4,0) 132(41.7,8.2) 133(42,0) 134(42.3,8.2) 135(42.6,0) 136(42.9,8.2) 137(43.2,0) 138(43.5,8.2) 139(43.8,0) 140(44.1,8.2) 141(44.4,0) 142(44.7,8.2) 143(45,0) 144(45.3,8.2) 145(45.6,0) 146(45.9,8.2) 147(46.2,0) 148(46.5,8.2) 149(46.8,0) 150(47.1,8.2) 151(47.4,0) 152(47.7,8.2) 153(48,0) 154(48.3,8.2) 155(48.6,0) 156(48.9,8.2) 157(49.2,0) 158(49.5,8.2) 159(49.8,0) 160(50.1,8.2) 161(50.4,0) 162(50.7,8.2) 163(51,0) 164(51.3,8.2) 165(51.6,0) 166(51.9,8.2) 167(52.2,0) 168(52.5,8.2) 169(52.8,0) 170(53.1,8.2) 171(53.4,0) 172(53.7,8.2) 173(54,0) 174(54.3,8.2) 175(54.6,0) 176(54.9,8.2) 177(55.2,0) 178(55.5,8.2) 179(55.8,0) 180(56.1,8.2) 181(56.4,0) 182(56.7,8.2) 183(57,0) 184(57.3,8.2) 185(57.6,0) 186(57.9,8.2) 187(58.2,0) 188(58.5,8.2) 189(58.8,0) 190(59.1,8.2) 191(59.4,0) 192(59.7,8.2) 193(60,0) 194(60.3,8.2) 195(60.6,0) 196(60.9,8.2) 197(61.2,0) 198(61.5,8.2) 199(61.8,0) 200(62.1,8.2) 201(62.4,0) 202(62.7,8.2) 203(63,0) 204(63.3,8.2)
  rect 3.505x4.597 smd: 205(-1.15,16.1) 206(64.45,16.1)
G5616ARZ1U_TQFN20_3X3
  oval 0.203x1.016 smd: 1(0,0) 2(0.4,0) 3(0.8,0) 4(1.2,0) 5(1.6,0) 11(1.6,2.975) 12(1.2,2.975) 13(0.8,2.975) 14(0.4,2.975) 15(0,2.975)
  oval 1.016x0.203 smd: 6(2.288,0.688) 7(2.288,1.088) 8(2.288,1.488) 9(2.288,1.888) 10(2.288,2.288) 16(-0.688,2.288) 17(-0.688,1.888) 18(-0.688,1.488) 19(-0.688,1.088) 20(-0.688,0.688)
  rect 1.6x1.6 smd: 21(0.8,1.488)
GM108-ES-S-A1_FCBGA_595P
  round 0.381 smd: A2(0.8,0) A3(1.6,0) A4(2.4,0) A6(4.1,0) A7(4.9,0) A9(6.58,0) A10(7.38,0) A12(9.06,0) A13(9.86,0) A15(11.54,0) A16(12.34,0) A18(14.02,0) A19(14.82,0) A21(16.5,0) A22(17.3,0) A24(19,0) A25(19.8,0) A26(20.6,0) AA1(0,-16.5) AA2(0.8,-16.5) AA3(1.6,-16.5) AA4(2.4,-16.5) AA5(3.2,-16.5) AA6(4.04,-16.5) AA7(4.9,-16.5) AA8(5.74,-16.5) AA9(6.58,-16.56) AA10(7.38,-16.56) AA12(9.06,-16.56) AA13(9.86,-16.56) AA14(10.7,-16.56) AA15(11.54,-16.56) AA16(12.34,-16.56) AA18(14.02,-16.56) AA19(14.82,-16.56) AA20(15.66,-16.5) AA21(16.5,-16.5) AA22(17.36,-16.5) AA23(18.2,-16.5) AA24(19,-16.5) AA25(19.8,-16.5) AA26(20.6,-16.5) AA27(21.4,-16.5) AB1(0,-17.3) AB2(0.8,-17.3) AB3(1.6,-17.3) AB4(2.4,-17.3) AB5(3.2,-17.3) AB6(4.1,-17.3) AB7(4.9,-17.36) AB8(5.74,-17.36) AB9(6.58,-17.36) AB10(7.38,-17.36) AB11(8.22,-17.36) AB12(9.06,-17.36) AB13(9.86,-17.36) AB14(10.7,-17.36) AB15(11.54,-17.36) AB16(12.34,-17.36) AB17(13.18,-17.36) AB18(14.02,-17.36) AB19(14.82,-17.36) AB20(15.66,-17.36) AB21(16.5,-17.36) AB22(17.3,-17.3) AB23(18.2,-17.3) AB24(19,-17.3) AB25(19.8,-17.3) AB26(20.6,-17.3) AB27(21.4,-17.3) AC2(0.8,-18.15) AC3(1.6,-18.15) AC4(2.4,-18.15) AC5(3.25,-18.15) AC6(4.1,-18.2) AC7(4.9,-18.2) AC8(5.74,-18.2) AC9(6.58,-18.2) AC10(7.38,-18.2) AC11(8.22,-18.2) AC12(9.06,-18.2) AC13(9.86,-18.2) AC14(10.7,-18.2) AC15(11.54,-18.2) AC16(12.34,-18.2) AC17(13.18,-18.2) AC18(14.02,-18.2) AC19(14.82,-18.2) AC20(15.66,-18.2) AC21(16.5,-18.2) AC22(17.3,-18.2) AC23(18.15,-18.15) AC24(19,-18.15) AC25(19.8,-18.15) AC26(20.6,-18.15) AD1(0,-19) AD2(0.8,-19) AD3(1.6,-19) AD4(2.4,-19) AD5(3.25,-19) AD6(4.1,-19) AD7(4.9,-19) AD8(5.74,-19) AD9(6.58,-19) AD10(7.38,-19) AD11(8.22,-19) AD12(9.06,-19) AD13(9.86,-19) AD14(10.7,-19) AD15(11.54,-19) AD16(12.34,-19) AD17(13.18,-19) AD18(14.02,-19) AD19(14.82,-19) AD20(15.66,-19) AD21(16.5,-19) AD22(17.3,-19) AD23(18.15,-19) AD24(19,-19) AD25(19.8,-19) AD26(20.6,-19) AD27(21.4,-19) AE1(0,-19.8) AE2(0.8,-19.8) AE3(1.6,-19.8) AE4(2.4,-19.8) AE5(3.25,-19.8) AE6(4.1,-19.8) AE7(4.9,-19.8) AE8(5.74,-19.8) AE9(6.58,-19.8) AE10(7.38,-19.8) AE11(8.22,-19.8) AE12(9.06,-19.8) AE13(9.86,-19.8) AE14(10.7,-19.8) AE15(11.54,-19.8) AE16(12.34,-19.8) AE17(13.18,-19.8) AE18(14.02,-19.8) AE19(14.82,-19.8) AE20(15.66,-19.8) AE21(16.5,-19.8) AE22(17.3,-19.8) AE23(18.15,-19.8) AE24(19,-19.8) AE25(19.8,-19.8) AE26(20.6,-19.8) AE27(21.4,-19.8) AF1(0,-20.6) AF2(0.8,-20.6) AF3(1.6,-20.6) AF4(2.4,-20.6) AF5(3.25,-20.6) AF6(4.1,-20.6) AF7(4.9,-20.6) AF8(5.74,-20.6) AF9(6.58,-20.6) AF10(7.38,-20.6) AF11(8.22,-20.6) AF12(9.06,-20.6) AF13(9.86,-20.6) AF14(10.7,-20.6) AF15(11.54,-20.6) AF16(12.34,-20.6) AF17(13.18,-20.6) AF18(14.02,-20.6) AF19(14.82,-20.6) AF20(15.66,-20.6) AF21(16.5,-20.6) AF22(17.3,-20.6) AF23(18.15,-20.6) AF24(19,-20.6) AF25(19.8,-20.6) AF26(20.6,-20.6) AF27(21.4,-20.6) AG2(0.8,-21.4) AG3(1.6,-21.4) AG4(2.4,-21.4) AG6(4.1,-21.4) AG7(4.9,-21.4) AG9(6.58,-21.4) AG10(7.38,-21.4) AG12(9.06,-21.4) AG13(9.86,-21.4) AG15(11.54,-21.4) AG16(12.34,-21.4) AG18(14.02,-21.4) AG19(14.82,-21.4) AG21(16.5,-21.4) AG22(17.3,-21.4) AG24(19,-21.4) AG25(19.8,-21.4) AG26(20.6,-21.4) B1(0,-0.8) B2(0.8,-0.8) B3(1.6,-0.8) B4(2.4,-0.8) B5(3.25,-0.8) B6(4.1,-0.8) B7(4.9,-0.8) B8(5.74,-0.8) B9(6.58,-0.8) B10(7.38,-0.8) B11(8.22,-0.8) B12(9.06,-0.8) B13(9.86,-0.8) B14(10.7,-0.8) B15(11.54,-0.8) B16(12.34,-0.8) B17(13.18,-0.8) B18(14.02,-0.8) B19(14.82,-0.8) B20(15.66,-0.8) B21(16.5,-0.8) B22(17.3,-0.8) B23(18.15,-0.8) B24(19,-0.8) B25(19.8,-0.8) B26(20.6,-0.8) B27(21.4,-0.8) C1(0,-1.6) C2(0.8,-1.6) C3(1.6,-1.6) C4(2.4,-1.6) C5(3.25,-1.6) C6(4.1,-1.6) C7(4.9,-1.6) C8(5.74,-1.6) C9(6.58,-1.6) C10(7.38,-1.6) C11(8.22,-1.6) C12(9.06,-1.6) C13(9.86,-1.6) C14(10.7,-1.6) C15(11.54,-1.6) C16(12.34,-1.6) C17(13.18,-1.6) C18(14.02,-1.6) C19(14.82,-1.6) C20(15.66,-1.6) C21(16.5,-1.6) C22(17.3,-1.6) C23(18.15,-1.6) C24(19,-1.6) C25(19.8,-1.6) C26(20.6,-1.6) C27(21.4,-1.6) D1(0,-2.4) D2(0.8,-2.4) D3(1.6,-2.4) D4(2.4,-2.4) D5(3.25,-2.4) D6(4.1,-2.4) D7(4.9,-2.4) D8(5.74,-2.4) D9(6.58,-2.4) D10(7.38,-2.4) D11(8.22,-2.4) D12(9.06,-2.4) D13(9.86,-2.4) D14(10.7,-2.4) D15(11.54,-2.4) D16(12.34,-2.4) D17(13.18,-2.4) D18(14.02,-2.4) D19(14.82,-2.4) D20(15.66,-2.4) D21(16.5,-2.4) D22(17.3,-2.4) D23(18.15,-2.4) D24(19,-2.4) D25(19.8,-2.4) D26(20.6,-2.4) D27(21.4,-2.4) E2(0.8,-3.25) E3(1.6,-3.25) E4(2.4,-3.25) E5(3.25,-3.25) E6(4.1,-3.2) E7(4.9,-3.2) E8(5.74,-3.2) E9(6.58,-3.2) E10(7.38,-3.2) E11(8.22,-3.2) E12(9.06,-3.2) E13(9.86,-3.2) E14(10.7,-3.2) E15(11.54,-3.2) E16(12.34,-3.2) E17(13.18,-3.2) E18(14.02,-3.2) E19(14.82,-3.2) E20(15.66,-3.2) E21(16.5,-3.2) E22(17.3,-3.2) E23(18.15,-3.25) E24(19,-3.25) E25(19.8,-3.25) E26(20.6,-3.25) F1(0,-4.1) F2(0.8,-4.1) F3(1.6,-4.1) F4(2.4,-4.1) F5(3.2,-4.1) F6(4.1,-4.1) F7(4.9,-4.04) F8(5.74,-4.04) F9(6.58,-4.04) F10(7.38,-4.04) F11(8.22,-4.04) F12(9.06,-4.04) F13(9.86,-4.04) F14(10.7,-4.04) F15(11.54,-4.04) F16(12.34,-4.04) F17(13.18,-4.04) F18(14.02,-4.04) F19(14.82,-4.04) F20(15.66,-4.04) F21(16.5,-4.04) F22(17.3,-4.1) F23(18.2,-4.1) F24(19,-4.1) F25(19.8,-4.1) F26(20.6,-4.1) F27(21.4,-4.1) G1(0,-4.9) G2(0.8,-4.9) G3(1.6,-4.9) G4(2.4,-4.9) G5(3.2,-4.9) G6(4.04,-4.9) G7(4.9,-4.9) G8(5.74,-4.9) G9(6.58,-4.84) G10(7.38,-4.84) G12(9.06,-4.84) G13(9.86,-4.84) G14(10.7,-4.84) G15(11.54,-4.84) G16(12.34,-4.84) G18(14.02,-4.84) G19(14.82,-4.84) G20(15.66,-4.9) G21(16.5,-4.9) G22(17.36,-4.9) G23(18.2,-4.9) G24(19,-4.9) G25(19.8,-4.9) G26(20.6,-4.9) G27(21.4,-4.9) H2(0.8,-5.74) H3(1.6,-5.74) H4(2.4,-5.74) H5(3.2,-5.74) H6(4.04,-5.74) H22(17.36,-5.74) H23(18.2,-5.74) H24(19,-5.74) H25(19.8,-5.74) H26(20.6,-5.74) J1(0,-6.58) J2(0.8,-6.58) J3(1.6,-6.58) J4(2.4,-6.58) J5(3.2,-6.58) J6(4.04,-6.58) J7(4.84,-6.58) J21(16.56,-6.58) J22(17.36,-6.58) J23(18.2,-6.58) J24(19,-6.58) J25(19.8,-6.58) J26(20.6,-6.58) J27(21.4,-6.58) K1(0,-7.38) K2(0.8,-7.38) K3(1.6,-7.38) K4(2.4,-7.38) K5(3.2,-7.38) K6(4.04,-7.38) K7(4.84,-7.38) K21(16.56,-7.38) K22(17.36,-7.38) K23(18.2,-7.38) K24(19,-7.38) K25(19.8,-7.38) K26(20.6,-7.38) K27(21.4,-7.38) L2(0.8,-8.22) L3(1.6,-8.22) L4(2.4,-8.22) L5(3.2,-8.22) L6(4.04,-8.22) L22(17.36,-8.22) L23(18.2,-8.22) L24(19,-8.22) L25(19.8,-8.22) L26(20.6,-8.22) M1(0,-9.06) M2(0.8,-9.06) M3(1.6,-9.06) M4(2.4,-9.06) M5(3.2,-9.06) M6(4.04,-9.06) M7(4.84,-9.06) M21(16.56,-9.06) M22(17.36,-9.06) M23(18.2,-9.06) M24(19,-9.06) M25(19.8,-9.06) M26(20.6,-9.06) M27(21.4,-9.06) N1(0,-9.86) N2(0.8,-9.86) N3(1.6,-9.86) N4(2.4,-9.86) N5(3.2,-9.86) N6(4.04,-9.86) N7(4.84,-9.86) N21(16.56,-9.86) N22(17.36,-9.86) N23(18.2,-9.86) N24(19,-9.86) N25(19.8,-9.86) N26(20.6,-9.86) N27(21.4,-9.86) P2(0.8,-10.7) P3(1.6,-10.7) P4(2.4,-10.7) P5(3.2,-10.7) P6(4.04,-10.7) P22(17.36,-10.7) P23(18.2,-10.7) P24(19,-10.7) P25(19.8,-10.7) P26(20.6,-10.7) R1(0,-11.54) R2(0.8,-11.54) R3(1.6,-11.54) R4(2.4,-11.54) R5(3.2,-11.54) R6(4.04,-11.54) R7(4.84,-11.54) R21(16.56,-11.54) R22(17.36,-11.54) R23(18.2,-11.54) R24(19,-11.54) R25(19.8,-11.54) R26(20.6,-11.54) R27(21.4,-11.54) T1(0,-12.34) T2(0.8,-12.34) T3(1.6,-12.34) T4(2.4,-12.34) T5(3.2,-12.34) T6(4.04,-12.34) T7(4.84,-12.34) T21(16.56,-12.34) T22(17.36,-12.34) T23(18.2,-12.34) T24(19,-12.34) T25(19.8,-12.34) T26(20.6,-12.34) T27(21.4,-12.34) U2(0.8,-13.18) U3(1.6,-13.18) U4(2.4,-13.18) U5(3.2,-13.18) U6(4.04,-13.18) U22(17.36,-13.18) U23(18.2,-13.18) U24(19,-13.18) U25(19.8,-13.18) U26(20.6,-13.18) V1(0,-14.02) V2(0.8,-14.02) V3(1.6,-14.02) V4(2.4,-14.02) V5(3.2,-14.02) V6(4.04,-14.02) V7(4.84,-14.02) V21(16.56,-14.02) V22(17.36,-14.02) V23(18.2,-14.02) V24(19,-14.02) V25(19.8,-14.02) V26(20.6,-14.02) V27(21.4,-14.02) W1(0,-14.82) W2(0.8,-14.82) W3(1.6,-14.82) W4(2.4,-14.82) W5(3.2,-14.82) W6(4.04,-14.82) W7(4.84,-14.82) W21(16.56,-14.82) W22(17.36,-14.82) W23(18.2,-14.82) W24(19,-14.82) W25(19.8,-14.82) W26(20.6,-14.82) W27(21.4,-14.82) Y2(0.8,-15.66) Y3(1.6,-15.66) Y4(2.4,-15.66) Y5(3.2,-15.66) Y6(4.04,-15.66) Y22(17.36,-15.66) Y23(18.2,-15.66) Y24(19,-15.66) Y25(19.8,-15.66) Y26(20.6,-15.66)
  round 0.406 smd: K10(6.7,-6.7) K11(7.7,-6.7) K12(8.7,-6.7) K13(9.7,-6.7) K14(10.7,-6.7) K15(11.7,-6.7) K16(12.7,-6.7) K17(13.7,-6.7) K18(14.7,-6.7) L10(6.7,-7.7) L11(7.7,-7.7) L12(8.7,-7.7) L13(9.7,-7.7) L14(10.7,-7.7) L15(11.7,-7.7) L16(12.7,-7.7) L17(13.7,-7.7) L18(14.7,-7.7) M10(6.7,-8.7) M11(7.7,-8.7) M12(8.7,-8.7) M13(9.7,-8.7) M14(10.7,-8.7) M15(11.7,-8.7) M16(12.7,-8.7) M17(13.7,-8.7) M18(14.7,-8.7) N10(6.7,-9.7) N11(7.7,-9.7) N12(8.7,-9.7) N13(9.7,-9.7) N14(10.7,-9.7) N15(11.7,-9.7) N16(12.7,-9.7) N17(13.7,-9.7) N18(14.7,-9.7) P10(6.7,-10.7) P11(7.7,-10.7) P12(8.7,-10.7) P13(9.7,-10.7) P14(10.7,-10.7) P15(11.7,-10.7) P16(12.7,-10.7) P17(13.7,-10.7) P18(14.7,-10.7) R10(6.7,-11.7) R11(7.7,-11.7) R12(8.7,-11.7) R13(9.7,-11.7) R14(10.7,-11.7) R15(11.7,-11.7) R16(12.7,-11.7) R17(13.7,-11.7) R18(14.7,-11.7) T10(6.7,-12.7) T11(7.7,-12.7) T12(8.7,-12.7) T13(9.7,-12.7) T14(10.7,-12.7) T15(11.7,-12.7) T16(12.7,-12.7) T17(13.7,-12.7) T18(14.7,-12.7) U10(6.7,-13.7) U11(7.7,-13.7) U12(8.7,-13.7) U13(9.7,-13.7) U14(10.7,-13.7) U15(11.7,-13.7) U16(12.7,-13.7) U17(13.7,-13.7) U18(14.7,-13.7) V10(6.7,-14.7) V11(7.7,-14.7) V12(8.7,-14.7) V13(9.7,-14.7) V14(10.7,-14.7) V15(11.7,-14.7) V16(12.7,-14.7) V17(13.7,-14.7) V18(14.7,-14.7)
H5TC4G63AFR-11C_FBGA_96P
  round 0.343 smd: A1(0,0) A2(0.8,0) A3(1.6,0) A7(4.801,0) A8(5.601,0) A9(6.401,0) B1(0,-0.8) B2(0.8,-0.8) B3(1.6,-0.8) B7(4.801,-0.8) B8(5.601,-0.8) B9(6.401,-0.8) C1(0,-1.6) C2(0.8,-1.6) C3(1.6,-1.6) C7(4.801,-1.6) C8(5.601,-1.6) C9(6.401,-1.6) D1(0,-2.4) D2(0.8,-2.4) D3(1.6,-2.4) D7(4.801,-2.4) D8(5.601,-2.4) D9(6.401,-2.4) E1(0,-3.2) E2(0.8,-3.2) E3(1.6,-3.2) E7(4.801,-3.2) E8(5.601,-3.2) E9(6.401,-3.2) F1(0,-4) F2(0.8,-4) F3(1.6,-4) F7(4.801,-4) F8(5.601,-4) F9(6.401,-4) G1(0,-4.801) G2(0.8,-4.801) G3(1.6,-4.801) G7(4.801,-4.801) G8(5.601,-4.801) G9(6.401,-4.801) H1(0,-5.601) H2(0.8,-5.601) H3(1.6,-5.601) H7(4.801,-5.601) H8(5.601,-5.601) H9(6.401,-5.601) J1(0,-6.401) J2(0.8,-6.401) J3(1.6,-6.401) J7(4.801,-6.401) J8(5.601,-6.401) J9(6.401,-6.401) K1(0,-7.201) K2(0.8,-7.201) K3(1.6,-7.201) K7(4.801,-7.201) K8(5.601,-7.201) K9(6.401,-7.201) L1(0,-8.001) L2(0.8,-8.001) L3(1.6,-8.001) L7(4.801,-8.001) L8(5.601,-8.001) L9(6.401,-8.001) M1(0,-8.801) M2(0.8,-8.801) M3(1.6,-8.801) M7(4.801,-8.801) M8(5.601,-8.801) M9(6.401,-8.801) N1(0,-9.601) N2(0.8,-9.601) N3(1.6,-9.601) N7(4.801,-9.601) N8(5.601,-9.601) N9(6.401,-9.601) P1(0,-10.401) P2(0.8,-10.401) P3(1.6,-10.401) P7(4.801,-10.401) P8(5.601,-10.401) P9(6.401,-10.401) R1(0,-11.201) R2(0.8,-11.201) R3(1.6,-11.201) R7(4.801,-11.201) R8(5.601,-11.201) R9(6.401,-11.201) T1(0,-12.002) T2(0.8,-12.002) T3(1.6,-12.002) T7(4.801,-12.002) T8(5.601,-12.002) T9(6.401,-12.002)
H_1P1N
  round 1.092 hole 1.092 unplated: (0,0)
H_2P3
  round 2.819 hole 2.311: 1(0,0)
H_2P3N
  round 2.311 hole 2.311 unplated: (0,0)
H_2P8
  round 3.302 hole 2.794: 1(0,0)
H_2P8X3P1N
  oval 2.794x3.099 hole 2.794x3.099 unplated: (0,0)
H_3P2
  round 3.708 hole 3.2: 1(0,0)
H_3P2X3P5
  oval 3.708x4.013 hole 3.2x3.505: 1(0,0)
H_3P3
  round 3.81 hole 3.302: 1(0,0)
H_3P5
  round 4.013 hole 3.505: 1(0,0)
H_6P0
  round 6.502 hole 5.994: 1(0,0)
H_6P6
  round 7.112 hole 6.604: 1(0,0)
HASWELL-MCP-E-ULT_BGA_1168P-T
  round 0.508 smd: A3(-1.137,0) A62(-38.036,0) AW1(0,22.042) AW63(-38.628,22.057) AY2(-0.543,22.628) AY62(-38.062,22.628) B2(-0.508,0.508) B63(-38.628,0.592) C1(0,1.137)
  round 0.381 smd: A4(-1.894,0) A5(-2.554,0) A6(-3.75,0) A59(-35.9,0) A60(-36.726,0) A61(-37.386,0) AA9(-5.032,11.576) AA21(-11.688,11.489) AA23(-13.115,11.489) AA58(-35.377,11.33) AB10(-5.476,12.053) AB20(-11.18,11.896) AB21(-11.688,12.302) AB22(-12.607,11.896) AB23(-13.115,12.302) AB57(-35.057,11.98) AC9(-5.032,12.529) AC20(-11.18,12.709) AC22(-12.607,12.709) AC58(-35.377,12.63) AD10(-5.476,13.005) AD21(-11.688,13.115) AD23(-13.115,13.115) AD57(-35.057,13.28) AE9(-5.032,13.481) AE10(-5.476,13.958) AE20(-11.18,13.521) AE21(-11.688,13.928) AE22(-12.607,13.521) AE23(-13.115,13.928) AE58(-35.377,13.931) AF9(-5.032,14.434) AF11(-6.059,14.282) AF12(-6.872,14.282) AF14(-7.685,14.282) AF15(-8.497,14.282) AF17(-9.31,14.282) AF18(-10.123,14.282) AF20(-10.936,14.282) AF22(-12.607,14.334) AG10(-5.653,14.79) AG11(-6.465,14.79) AG13(-7.278,14.79) AG14(-8.091,14.79) AG16(-8.904,14.79) AG17(-9.717,14.79) AG19(-10.529,14.79) AG20(-11.342,14.79) AG23(-13.115,14.741) AG57(-35.057,14.581) AG58(-35.692,15.009) AH22(-12.607,15.147) AH24(-13.92,15.289) AH26(-15.22,15.289) AH28(-16.521,15.289) AH30(-17.821,15.289) AH32(-19.122,15.289) AH34(-20.422,15.289) AH36(-21.723,15.289) AH38(-23.023,15.289) AH40(-24.324,15.289) AH42(-25.624,15.289) AH44(-26.925,15.289) AH46(-28.225,15.289) AH49(-29.526,15.289) AH51(-30.826,15.289) AH53(-32.127,15.289) AH55(-33.427,15.289) AH57(-34.728,15.289) AJ23(-13.115,15.553) AJ25(-14.57,15.614) AJ27(-15.871,15.614) AJ29(-17.171,15.614) AJ31(-18.472,15.614) AJ33(-19.772,15.614) AJ35(-21.073,15.614) AJ37(-22.373,15.614) AJ39(-23.674,15.614) AJ41(-24.974,15.614) AJ43(-26.275,15.614) AJ45(-27.575,15.614) AJ47(-28.875,15.614) AJ50(-30.176,15.614) AJ52(-31.476,15.614) AJ54(-32.777,15.614) AJ56(-34.077,15.614) AJ58(-35.378,15.614) AT1(0,19.997) AT63(-38.628,19.848) AU1(0,20.657) AU63(-38.628,20.673) AV1(0,21.318) AV2(-0.66,21.308) AV62(-37.978,21.318) AV63(-38.628,21.333) AW2(-0.66,21.968) AW3(-1.321,21.968) AW61(-37.328,21.978) AW62(-37.978,21.978) AY3(-1.267,22.628) AY4(-1.928,22.628) AY5(-2.588,22.628) AY59(-36.088,22.628) AY60(-36.748,22.628) AY61(-37.409,22.628) B3(-1.259,0.65) B61(-37.315,0.66) B62(-37.978,0.724) C2(-0.65,1.259) C62(-37.978,1.384) C63(-38.628,1.316) D1(0,1.861) D63(-38.628,1.976) E1(0,2.522) E23(-13.333,2.601) E25(-14.714,2.601) E27(-15.84,2.601) E29(-17.221,2.601) E31(-18.348,2.601) E33(-19.729,2.601) E35(-20.855,2.601) E37(-22.236,2.601) E39(-23.363,2.601) E41(-24.744,2.601) E43(-25.87,2.601) E45(-27.251,2.601) E47(-28.378,2.601) E49(-29.759,2.601) E51(-30.885,2.601) E53(-32.266,2.601) E55(-33.393,2.601) E57(-34.774,2.601) E63(-38.628,2.647) F1(0,3.436) F22(-12.717,3.058) F24(-14.023,3.126) F26(-15.277,3.126) F28(-16.531,3.126) F30(-17.785,3.126) F32(-19.038,3.126) F34(-20.292,3.126) F36(-21.546,3.126) F38(-22.8,3.126) F40(-24.053,3.126) F42(-25.307,3.126) F44(-26.561,3.126) F46(-27.815,3.126) F48(-29.068,3.126) F50(-30.322,3.126) F52(-31.576,3.126) F54(-32.83,3.126) F56(-34.083,3.126) F58(-35.377,3.126) G22(-12.607,3.768) G23(-13.333,3.451) G25(-14.714,3.451) G27(-15.84,3.451) G29(-17.221,3.451) G31(-18.348,3.451) G33(-19.729,3.451) G35(-20.855,3.451) G37(-22.236,3.451) G39(-23.363,3.451) G41(-24.744,3.451) G43(-25.87,3.451) G45(-27.251,3.451) G47(-28.378,3.451) G49(-29.759,3.451) G51(-30.885,3.451) G53(-32.266,3.451) G55(-33.393,3.451) G57(-34.774,3.451) H22(-12.607,4.581) H23(-13.115,4.174) H57(-35.057,4.101) J22(-12.607,5.393) J23(-13.115,4.987) J58(-35.377,4.827) K9(-5.032,5.861) K10(-5.935,5.7) K12(-6.888,5.7) K14(-7.84,5.7) K16(-8.793,5.7) K18(-9.745,5.7) K19(-10.698,5.7) K21(-11.65,5.7) K23(-13.115,5.8) K57(-35.057,5.478) L10(-5.476,6.338) L11(-6.412,6.144) L13(-7.364,6.144) L15(-8.317,6.144) L17(-9.269,6.144) L18(-10.222,6.144) L20(-11.18,6.206) L22(-12.607,6.206) L58(-35.377,6.128) M9(-5.032,6.814) M20(-11.18,7.019) M21(-11.688,6.613) M22(-12.607,7.019) M23(-13.115,6.613) M57(-35.057,6.778) N10(-5.476,7.29) N21(-11.688,7.425) N23(-13.115,7.425) N58(-35.377,7.428) P9(-5.032,7.766) P20(-11.18,7.832) P22(-12.607,7.832) P57(-35.057,8.078) R10(-5.476,8.243) R20(-11.18,8.645) R21(-11.688,8.238) R22(-12.607,8.645) R23(-13.115,8.238) T9(-5.032,8.719) T21(-11.688,9.051) T23(-13.115,9.051) T58(-35.377,8.729) U9(-5.032,9.671) U10(-5.476,9.195) U20(-11.18,9.457) U22(-12.607,9.457) U57(-35.057,9.379) V10(-5.476,10.148) V21(-11.688,9.864) V23(-13.115,9.864) V58(-35.377,10.029) W9(-5.032,10.624) W20(-11.18,10.27) W21(-11.688,10.677) W22(-12.607,10.27) W23(-13.115,10.677) W57(-35.057,10.679) Y10(-5.476,11.1) Y20(-11.18,11.083) Y22(-12.607,11.083)
  round 0.305 smd: A8(-4.538,0) A9(-5.452,0) A11(-6.367,0) A12(-7.116,0) A14(-8.03,0) A15(-8.945,0) A17(-9.694,0) A18(-10.608,0) A20(-11.523,0) A21(-12.272,0) A23(-13.186,0) A24(-14.023,0.325) A25(-14.714,0) A27(-15.84,0) A28(-16.531,0.325) A29(-17.221,0) A31(-18.348,0) A32(-19.038,0.325) A33(-19.729,0) A35(-20.855,0) A36(-21.546,0.325) A37(-22.236,0) A39(-23.363,0) A40(-24.053,0.325) A41(-24.744,0) A43(-25.87,0) A44(-26.561,0.325) A45(-27.251,0) A47(-28.378,0) A48(-29.068,0.325) A49(-29.759,0) A51(-30.885,0) A52(-31.576,0.325) A53(-32.266,0) A55(-33.393,0) A56(-34.083,0.325) A57(-34.774,0) AA1(0,11.717) AA2(-0.65,11.717) AA3(-1.3,11.678) AA4(-1.951,11.678) AA59(-36.027,11.638) AA60(-36.678,11.638) AA61(-37.328,11.638) AA62(-37.978,11.676) AA63(-38.628,11.676) AB5(-2.637,12.053) AB6(-3.287,12.053) AB7(-3.937,12.053) AB8(-4.587,12.053) AC1(0,12.466) AC2(-0.65,12.466) AC3(-1.3,12.504) AC4(-1.951,12.504) AC59(-36.027,12.464) AC60(-36.678,12.464) AC61(-37.328,12.464) AC62(-37.978,12.426) AC63(-38.628,12.426) AD1(0,13.215) AD2(-0.65,13.215) AD3(-1.3,13.177) AD4(-1.951,13.177) AD5(-2.637,13.005) AD6(-3.287,13.005) AD7(-3.937,13.005) AD8(-4.587,13.005) AD59(-36.027,13.137) AD60(-36.678,13.137) AD61(-37.328,13.137) AD62(-37.978,13.175) AD63(-38.628,13.175) AE5(-2.637,13.958) AE6(-3.287,13.958) AE7(-3.937,13.958) AE8(-4.587,13.958) AE59(-36.027,13.962) AE60(-36.678,13.962) AE61(-37.328,13.962) AE62(-37.978,13.924) AE63(-38.628,13.924) AF1(0,13.964) AF2(-0.65,13.964) AF3(-1.3,14.003) AF4(-1.951,14.003) AG1(0,14.714) AG2(-0.65,14.714) AG3(-1.3,14.676) AG4(-1.951,14.676) AG5(-2.637,14.91) AG6(-3.287,14.91) AG7(-3.937,14.91) AG8(-4.587,14.91) AG21(-11.955,15.122) AG60(-36.352,14.602) AG61(-37.003,14.602) AG62(-37.653,14.602) AG63(-38.303,14.602) AH1(0,15.463) AH2(-0.65,15.463) AH3(-1.3,15.501) AH4(-1.951,15.501) AH10(-5.653,15.476) AH11(-6.465,15.476) AH13(-7.278,15.476) AH14(-8.091,15.476) AH16(-8.904,15.476) AH17(-9.717,15.476) AH19(-10.529,15.476) AH20(-11.342,15.476) AH60(-36.678,15.278) AH61(-37.328,15.278) AH62(-37.978,15.278) AH63(-38.628,15.278) AJ5(-2.637,15.863) AJ6(-3.287,15.863) AJ7(-3.937,15.863) AJ8(-4.587,15.863) AJ10(-5.653,16.126) AJ11(-6.465,16.126) AJ13(-7.278,16.126) AJ14(-8.091,16.126) AJ60(-36.352,15.954) AJ61(-37.003,15.954) AJ62(-37.653,15.954) AJ63(-38.303,15.954) AK1(0,16.212) AK2(-0.65,16.212) AK3(-1.3,16.174) AK4(-1.951,16.174) AK8(-4.303,16.451) AK18(-9.848,16.266) AK20(-10.801,16.266) AK21(-11.753,16.266) AK60(-36.678,16.523) AK61(-37.328,16.523) AK62(-37.978,16.629) AK63(-38.628,16.629) AL1(0,16.962) AL2(-0.65,16.962) AL3(-1.3,17) AL4(-1.951,17) AL5(-2.901,16.776) AL7(-3.739,16.776) AL8(-4.303,17.101) AL10(-5.658,16.776) AL11(-6.221,17.101) AL13(-7.576,16.776) AL15(-8.14,17.101) AL17(-9.222,16.583) AL18(-9.848,16.916) AL20(-10.801,16.916) AL21(-11.753,16.916) AL22(-12.706,16.916) AL23(-13.529,16.916) AL25(-14.504,16.916) AL26(-15.456,16.916) AL28(-16.409,16.916) AL29(-17.361,16.916) AL31(-18.26,16.591) AL32(-18.824,16.916) AL33(-19.726,16.916) AL35(-20.729,16.916) AL36(-21.58,16.916) AL38(-22.634,16.916) AL39(-23.542,16.591) AL40(-24.131,16.916) AL42(-24.944,16.916) AL43(-25.897,16.916) AL45(-26.874,16.916) AL46(-27.802,16.916) AL48(-28.856,16.916) AL49(-29.757,16.916) AL51(-30.761,16.916) AL52(-31.583,16.916) AL54(-32.61,16.916) AL55(-33.562,16.916) AL57(-34.509,16.916) AL58(-35.408,16.916) AL60(-36.352,17.169) AL61(-37.003,17.169) AM1(0,17.711) AM2(-0.65,17.711) AM3(-1.3,17.673) AM4(-1.951,17.673) AM5(-2.901,17.426) AM7(-3.739,17.426) AM8(-4.303,17.752) AM10(-5.658,17.426) AM11(-6.221,17.752) AM13(-7.576,17.426) AM15(-8.14,17.752) AM17(-9.222,17.233) AM18(-9.848,17.567) AM20(-10.801,17.567) AM21(-11.753,17.567) AM22(-12.706,17.567) AM23(-13.529,17.567) AM25(-14.504,17.567) AM26(-15.456,17.567) AM28(-16.409,17.567) AM29(-17.361,17.567) AM31(-18.26,17.242) AM32(-18.824,17.567) AM33(-19.726,17.567) AM35(-20.729,17.567) AM36(-21.58,17.567) AM38(-22.634,17.567) AM40(-24.131,17.567) AM42(-24.944,17.567) AM43(-25.897,17.567) AM45(-26.874,17.567) AM46(-27.802,17.567) AM48(-28.856,17.567) AM49(-29.757,17.567) AM51(-30.761,17.567) AM52(-31.583,17.567) AM54(-32.61,17.567) AM55(-33.562,17.567) AM57(-34.509,17.567) AM58(-35.408,17.567) AM60(-36.678,17.816) AM61(-37.328,17.816) AM62(-37.978,17.709) AM63(-38.628,17.709) AN1(0,18.46) AN2(-0.65,18.46) AN3(-1.3,18.498) AN4(-1.951,18.498) AN5(-2.901,18.077) AN7(-3.739,18.077) AN8(-4.303,18.402) AN10(-5.658,18.077) AN11(-6.221,18.402) AN13(-7.576,18.077) AN15(-8.14,18.402) AN17(-9.222,17.883) AN18(-9.848,18.217) AN20(-10.801,18.217) AN21(-11.753,18.217) AN22(-12.706,18.217) AN23(-13.529,18.217) AN25(-14.504,18.217) AN26(-15.456,18.217) AN28(-16.409,18.217) AN29(-17.361,18.217) AN31(-18.26,17.892) AN32(-18.824,18.217) AN33(-19.726,18.217) AN35(-20.729,18.217) AN36(-21.58,18.217) AN38(-22.634,18.217) AN39(-23.542,17.892) AN40(-24.131,18.217) AN42(-24.944,18.217) AN43(-25.897,18.217) AN45(-26.874,18.217) AN46(-27.802,18.217) AN48(-28.856,18.217) AN49(-29.757,18.217) AN51(-30.761,18.217) AN52(-31.583,18.217) AN54(-32.61,18.217) AN55(-33.562,18.217) AN57(-34.509,18.217) AN58(-35.408,18.217) AN60(-36.352,18.385) AN61(-37.003,18.385) AN62(-37.653,18.385) AN63(-38.303,18.385) AP1(0,19.21) AP2(-0.65,19.21) AP3(-1.3,19.171) AP4(-1.951,19.171) AP5(-2.901,18.727) AP7(-3.739,18.727) AP8(-4.303,19.052) AP10(-5.658,18.727) AP11(-6.221,19.052) AP13(-7.576,18.727) AP15(-8.14,19.052) AP17(-9.222,18.533) AP18(-9.848,18.867) AP20(-10.801,18.867) AP21(-11.753,18.867) AP22(-12.706,18.867) AP23(-13.529,18.867) AP25(-14.504,18.867) AP26(-15.456,18.867) AP28(-16.409,18.867) AP29(-17.361,18.867) AP31(-18.26,18.542) AP32(-18.824,18.867) AP33(-19.726,18.867) AP35(-20.729,18.867) AP36(-21.58,18.867) AP38(-22.634,18.867) AP39(-23.542,18.542) AP40(-24.131,18.867) AP42(-24.944,18.867) AP43(-25.897,18.867) AP45(-26.874,18.867) AP46(-27.802,18.867) AP48(-28.856,18.867) AP49(-29.757,18.867) AP51(-30.761,18.867) AP52(-31.583,18.867) AP54(-32.61,18.867) AP55(-33.562,18.867) AP57(-34.509,18.867) AP58(-35.408,18.867) AP60(-36.678,19.06) AP61(-37.328,19.06) AP62(-37.978,19.06) AP63(-38.628,19.06) AR5(-2.901,19.377) AR7(-3.739,19.377) AR8(-4.303,19.702) AR10(-5.658,19.377) AR11(-6.221,19.702) AR13(-7.576,19.377) AR15(-8.14,19.702) AR17(-9.222,19.184) AR18(-9.848,19.517) AR20(-10.801,19.517) AR21(-11.753,19.517) AR22(-12.706,19.517) AR23(-13.529,19.517) AR25(-14.504,19.517) AR26(-15.456,19.517) AR28(-16.409,19.517) AR29(-17.361,19.517) AR31(-18.26,19.192) AR32(-18.824,19.517) AR33(-19.726,19.517) AR35(-20.729,19.517) AR36(-21.58,19.517) AR38(-22.634,19.517) AR39(-23.542,19.192) AR40(-24.131,19.517) AR42(-24.944,19.517) AR43(-25.897,19.517) AR45(-26.874,19.517) AR46(-27.802,19.517) AR48(-28.856,19.517) AR49(-29.757,19.517) AR51(-30.761,19.517) AR52(-31.583,19.517) AR54(-32.61,19.517) AR55(-33.562,19.517) AR57(-34.509,19.517) AR58(-35.408,19.517) AT2(-0.65,19.959) AT3(-1.3,19.997) AT4(-1.951,19.997) AT5(-2.901,20.027) AT7(-3.739,20.027) AT10(-5.658,20.027) AT13(-7.576,20.027) AT35(-20.437,20.22) AT37(-22.011,20.22) AT40(-23.586,20.22) AT42(-25.161,20.22) AT43(-26.736,20.22) AT46(-28.311,20.22) AT49(-29.912,20.248) AT61(-37.003,19.634) AT62(-37.812,19.69) AU2(-0.655,20.647) AU3(-1.315,20.647) AU4(-1.976,20.647) AU6(-3.337,20.678) AU7(-4.163,20.678) AU8(-4.836,20.678) AU10(-5.661,20.678) AU11(-6.335,20.678) AU12(-7.16,20.678) AU14(-7.833,20.678) AU15(-8.659,20.678) AU16(-9.222,20.353) AU17(-9.86,20.678) AU18(-10.536,20.353) AU19(-11.105,20.678) AU20(-11.751,20.353) AU21(-12.397,20.678) AU22(-12.966,20.353) AU23(-13.642,20.678) AU24(-14.318,20.353) AU25(-14.993,20.678) AU26(-15.669,20.353) AU27(-16.238,20.678) AU28(-16.884,20.353) AU29(-17.531,20.678) AU30(-18.1,20.353) AU31(-18.775,20.678) AU33(-19.372,20.33) AU34(-19.974,20.678) AU35(-20.899,20.678) AU36(-21.549,20.678) AU37(-22.474,20.678) AU39(-23.124,20.678) AU40(-24.048,20.678) AU41(-24.699,20.678) AU42(-25.623,20.678) AU43(-26.274,20.678) AU44(-27.198,20.678) AU46(-27.848,20.678) AU47(-28.773,20.678) AU49(-29.423,20.678) AU50(-30.4,20.678) AU51(-30.98,20.353) AU52(-31.656,20.678) AU53(-32.331,20.353) AU54(-32.9,20.678) AU55(-33.547,20.353) AU56(-34.193,20.678) AU57(-34.762,20.353) AU58(-35.438,20.678) AU59(-36.002,20.353) AU60(-36.566,20.678) AU61(-37.277,20.401) AU62(-37.978,20.663) AV3(-1.321,21.308) AV4(-1.976,21.308) AV5(-2.664,21.328) AV6(-3.337,21.328) AV7(-4.163,21.328) AV8(-4.836,21.328) AV10(-5.661,21.328) AV11(-6.335,21.328) AV12(-7.16,21.328) AV14(-7.833,21.328) AV15(-8.659,21.328) AV16(-9.222,21.003) AV17(-9.86,21.328) AV18(-10.536,21.003) AV19(-11.105,21.328) AV20(-11.751,21.003) AV21(-12.397,21.328) AV22(-12.966,21.003) AV23(-13.642,21.328) AV24(-14.318,21.003) AV25(-14.993,21.328) AV26(-15.669,21.003) AV27(-16.238,21.328) AV28(-16.884,21.003) AV29(-17.531,21.328) AV30(-18.1,21.003) AV31(-18.775,21.328) AV33(-19.4,21.003) AV34(-20.024,21.328) AV35(-20.849,21.328) AV36(-21.599,21.328) AV37(-22.424,21.328) AV39(-23.173,21.328) AV40(-23.999,21.328) AV41(-24.748,21.328) AV42(-25.574,21.328) AV43(-26.323,21.328) AV44(-27.149,21.328) AV46(-27.898,21.328) AV47(-28.723,21.328) AV49(-29.473,21.328) AV50(-30.298,21.328) AV51(-30.98,21.003) AV52(-31.656,21.328) AV53(-32.331,21.003) AV54(-32.9,21.328) AV55(-33.547,21.003) AV56(-34.193,21.328) AV57(-34.762,21.003) AV58(-35.438,21.328) AV59(-36.002,21.003) AV60(-36.566,21.328) AV61(-37.302,21.051) AW4(-1.976,21.968) AW5(-2.626,21.978) AW6(-3.375,21.978) AW7(-4.125,21.978) AW8(-4.874,21.978) AW10(-5.623,21.978) AW11(-6.373,21.978) AW12(-7.122,21.978) AW14(-7.871,21.978) AW15(-8.621,21.978) AW16(-9.222,21.653) AW17(-9.86,21.978) AW18(-10.536,21.653) AW19(-11.211,21.978) AW21(-12.291,21.978) AW22(-12.966,21.653) AW23(-13.642,21.978) AW24(-14.318,21.653) AW25(-14.993,21.978) AW26(-15.669,21.653) AW27(-16.345,21.978) AW29(-17.424,21.978) AW30(-18.1,21.653) AW31(-18.775,21.978) AW33(-19.451,21.653) AW34(-20.024,21.978) AW35(-20.849,21.978) AW36(-21.599,21.978) AW37(-22.424,21.978) AW39(-23.173,21.978) AW40(-23.999,21.978) AW41(-24.748,21.978) AW42(-25.574,21.978) AW43(-26.323,21.978) AW44(-27.149,21.978) AW46(-27.898,21.978) AW47(-28.723,21.978) AW49(-29.473,21.978) AW50(-30.298,21.978) AW51(-30.98,21.653) AW52(-31.656,21.978) AW53(-32.331,21.653) AW54(-33.007,21.978) AW56(-34.087,21.978) AW57(-34.762,21.653) AW58(-35.438,21.978) AW59(-36.002,21.653) AW60(-36.566,21.978) AY6(-3.375,22.628) AY7(-4.125,22.628) AY8(-4.874,22.628) AY10(-5.623,22.628) AY11(-6.373,22.628) AY12(-7.122,22.628) AY14(-7.871,22.628) AY15(-8.621,22.628) AY16(-9.184,22.303) AY17(-9.86,22.628) AY18(-10.536,22.303) AY19(-11.211,22.628) AY21(-12.291,22.628) AY22(-12.966,22.303) AY23(-13.642,22.628) AY24(-14.318,22.303) AY25(-14.993,22.628) AY26(-15.669,22.303) AY27(-16.345,22.628) AY29(-17.424,22.628) AY30(-18.1,22.303) AY31(-18.775,22.628) AY33(-19.451,22.303) AY34(-20.024,22.628) AY35(-20.849,22.628) AY36(-21.599,22.628) AY37(-22.424,22.628) AY39(-23.173,22.628) AY40(-23.999,22.628) AY41(-24.748,22.628) AY42(-25.574,22.628) AY43(-26.323,22.628) AY44(-27.149,22.628) AY46(-27.898,22.628) AY47(-28.723,22.628) AY49(-29.473,22.628) AY50(-30.298,22.628) AY51(-30.98,22.303) AY52(-31.656,22.628) AY53(-32.331,22.303) AY54(-33.007,22.628) AY56(-34.087,22.628) AY57(-34.762,22.303) AY58(-35.438,22.628) B4(-1.922,0.65) B5(-3.138,0.643) B6(-4.119,0.643) B8(-4.891,0.643) B9(-5.716,0.643) B11(-6.697,0.643) B12(-7.469,0.643) B14(-8.294,0.643) B15(-9.275,0.643) B17(-10.047,0.643) B18(-10.872,0.643) B20(-11.853,0.643) B21(-12.272,1.196) B22(-12.625,0.643) B23(-13.451,0.643) B24(-14.023,0.975) B25(-14.714,0.65) B26(-15.277,0.975) B27(-15.84,0.65) B28(-16.531,0.975) B29(-17.221,0.65) B30(-17.785,0.975) B31(-18.348,0.65) B32(-19.038,0.975) B33(-19.729,0.65) B34(-20.292,0.975) B35(-20.855,0.65) B36(-21.546,0.975) B37(-22.236,0.65) B38(-22.8,0.975) B39(-23.363,0.65) B40(-24.053,0.975) B41(-24.744,0.65) B42(-25.307,0.975) B43(-25.87,0.65) B44(-26.561,0.975) B45(-27.251,0.65) B46(-27.815,0.975) B47(-28.378,0.65) B48(-29.068,0.975) B49(-29.759,0.65) B50(-30.322,0.975) B51(-30.885,0.65) B52(-31.576,0.975) B53(-32.266,0.65) B54(-32.83,0.975) B55(-33.393,0.65) B56(-34.083,0.975) B57(-34.774,0.65) B58(-35.337,0.975) B59(-35.9,0.65) B60(-36.665,0.66) C3(-1.302,1.302) C4(-2.118,1.272) C5(-2.772,1.196) C6(-3.776,1.196) C8(-4.538,1.196) C9(-5.351,1.196) C11(-6.354,1.196) C12(-7.116,1.196) C14(-7.929,1.196) C15(-8.932,1.196) C17(-9.694,1.196) C18(-10.507,1.196) C20(-11.51,1.196) C21(-11.891,1.786) C22(-12.678,1.786) C23(-13.085,1.196) C24(-14.051,2.032) C25(-14.714,1.3) C26(-15.277,1.626) C27(-15.84,1.3) C28(-16.558,2.032) C29(-17.221,1.3) C30(-17.785,1.626) C31(-18.348,1.3) C32(-19.066,2.032) C33(-19.729,1.3) C34(-20.292,1.626) C35(-20.855,1.3) C36(-21.573,2.032) C37(-22.236,1.3) C38(-22.8,1.626) C39(-23.363,1.3) C40(-24.081,2.032) C41(-24.744,1.3) C42(-25.307,1.626) C43(-25.87,1.3) C44(-26.588,2.032) C45(-27.251,1.3) C46(-27.815,1.626) C47(-28.378,1.3) C48(-29.07,2.032) C49(-29.759,1.3) C50(-30.322,1.626) C51(-30.885,1.3) C52(-31.578,1.991) C53(-32.266,1.3) C54(-32.83,1.626) C55(-33.393,1.3) C56(-34.085,1.991) C57(-34.774,1.3) C58(-35.337,1.626) C59(-35.9,1.3) C61(-37.003,1.237) D2(-0.65,2.075) D3(-1.3,2.037) D5(-2.678,1.842) D6(-3.369,1.786) D8(-4.157,1.786) D9(-4.944,1.786) D11(-5.852,1.786) D12(-6.735,1.786) D14(-7.522,1.786) D15(-8.43,1.786) D17(-9.313,1.786) D18(-10.1,1.786) D20(-11.008,1.786) D21(-12.235,2.423) D23(-13.377,1.786) D25(-14.714,1.951) D26(-15.277,2.276) D27(-15.84,1.951) D29(-17.221,1.951) D30(-17.785,2.276) D31(-18.348,1.951) D33(-19.729,1.951) D34(-20.292,2.276) D35(-20.855,1.951) D37(-22.236,1.951) D38(-22.8,2.276) D39(-23.363,1.951) D41(-24.744,1.951) D42(-25.307,2.276) D43(-25.87,1.951) D45(-27.251,1.951) D46(-27.815,2.276) D47(-28.378,1.951) D49(-29.759,1.951) D50(-30.322,2.276) D51(-30.885,1.951) D53(-32.266,1.951) D54(-32.83,2.276) D55(-33.393,1.951) D57(-34.774,1.951) D58(-35.337,2.276) D59(-35.9,1.951) D60(-36.678,1.801) D61(-37.328,1.801) D62(-37.978,2.035) E2(-0.65,2.725) E3(-1.3,2.687) E4(-1.951,2.687) E5(-2.602,2.619) E6(-3.554,2.619) E8(-4.507,2.619) E10(-5.459,2.619) E11(-6.412,2.619) E13(-7.364,2.619) E15(-8.317,2.619) E17(-9.269,2.619) E18(-10.222,2.619) E20(-11.174,2.619) E59(-36.027,2.647) E60(-36.678,2.647) E61(-37.328,2.647) E62(-37.978,2.685) F2(-0.65,3.474) F3(-1.3,3.512) F4(-1.951,3.512) F5(-2.602,3.269) F6(-3.554,3.269) F8(-4.507,3.269) F10(-5.459,3.269) F11(-6.412,3.269) F13(-7.364,3.269) F15(-8.317,3.269) F17(-9.269,3.269) F18(-10.222,3.269) F20(-11.174,3.269) F59(-36.027,3.472) F60(-36.678,3.472) F61(-37.328,3.472) F62(-37.978,3.434) F63(-38.628,3.434) G1(0,4.224) G2(-0.65,4.224) G3(-1.3,4.185) G4(-1.951,4.185) G5(-2.602,3.919) G6(-3.554,3.919) G8(-4.507,3.919) G10(-5.459,3.919) G11(-6.412,3.919) G13(-7.364,3.919) G15(-8.317,3.919) G17(-9.269,3.919) G18(-10.222,3.919) G20(-11.174,3.919) H5(-2.602,4.569) H6(-3.554,4.569) H8(-4.507,4.569) H10(-5.459,4.569) H11(-6.412,4.569) H13(-7.364,4.569) H15(-8.317,4.569) H17(-9.269,4.569) H18(-10.222,4.569) H20(-11.174,4.569) H59(-36.027,4.145) H60(-36.678,4.145) H61(-37.328,4.145) H62(-37.978,4.183) H63(-38.628,4.183) J1(0,4.973) J2(-0.65,4.973) J3(-1.3,5.011) J4(-1.951,5.011) J5(-2.627,5.22) J6(-3.567,5.22) J8(-4.507,5.22) J10(-5.459,5.22) J11(-6.412,5.22) J13(-7.364,5.22) J15(-8.317,5.22) J17(-9.269,5.22) J18(-10.222,5.22) J20(-11.174,5.22) J21(-12.095,4.986) J59(-36.027,4.971) J60(-36.678,4.971) J61(-37.328,4.971) J62(-37.978,4.933) J63(-38.628,4.933) K1(0,5.722) K2(-0.65,5.722) K3(-1.3,5.684) K4(-1.951,5.684) K59(-36.027,5.644) K60(-36.678,5.644) K61(-37.328,5.644) K62(-37.978,5.682) K63(-38.628,5.682) L1(0,6.471) L2(-0.65,6.471) L3(-1.3,6.51) L4(-1.951,6.51) L5(-2.637,6.338) L6(-3.287,6.338) L7(-3.937,6.338) L8(-4.587,6.338) L59(-36.027,6.469) L60(-36.678,6.469) L61(-37.328,6.469) L62(-37.978,6.431) L63(-38.628,6.431) N1(0,7.221) N2(-0.65,7.221) N3(-1.3,7.183) N4(-1.951,7.183) N5(-2.637,7.29) N6(-3.287,7.29) N7(-3.937,7.29) N8(-4.587,7.29) N59(-36.027,7.142) N60(-36.678,7.142) N61(-37.328,7.142) N62(-37.978,7.181) N63(-38.628,7.181) P1(0,7.97) P2(-0.65,7.97) P3(-1.3,8.008) P4(-1.951,8.008) P59(-36.027,7.968) P60(-36.678,7.968) P61(-37.328,7.968) P62(-37.978,7.93) P63(-38.628,7.93) R5(-2.637,8.243) R6(-3.287,8.243) R7(-3.937,8.243) R8(-4.587,8.243) T1(0,8.719) T2(-0.65,8.719) T3(-1.3,8.681) T4(-1.951,8.681) T59(-36.027,8.641) T60(-36.678,8.641) T61(-37.328,8.641) T62(-37.978,8.679) T63(-38.628,8.679) U1(0,9.469) U2(-0.65,9.469) U3(-1.3,9.507) U4(-1.951,9.507) U5(-2.637,9.195) U6(-3.287,9.195) U7(-3.937,9.195) U8(-4.587,9.195) U59(-36.027,9.467) U60(-36.678,9.467) U61(-37.328,9.467) U62(-37.978,9.428) U63(-38.628,9.428) V1(0,10.218) V2(-0.65,10.218) V3(-1.3,10.18) V4(-1.951,10.18) V5(-2.637,10.148) V6(-3.287,10.148) V7(-3.937,10.148) V8(-4.587,10.148) V59(-36.027,10.14) V60(-36.678,10.14) V61(-37.328,10.14) V62(-37.978,10.178) V63(-38.628,10.178) Y1(0,10.967) Y2(-0.65,10.967) Y3(-1.3,11.005) Y4(-1.951,11.005) Y5(-2.637,11.1) Y6(-3.287,11.1) Y7(-3.937,11.1) Y8(-4.587,11.1) Y59(-36.027,10.965) Y60(-36.678,10.965) Y61(-37.328,10.965) Y62(-37.978,10.927) Y63(-38.628,10.927)
  round 0.33 smd: AK22(-12.655,16.266) AK23(-13.529,16.266) AK25(-14.504,16.266) AK26(-15.456,16.266) AK28(-16.409,16.266) AK29(-17.311,16.266) AK32(-18.824,16.266) AK33(-19.726,16.266) AK35(-20.729,16.266) AK36(-21.58,16.266) AK38(-22.609,16.266) AK40(-24.106,16.266) AK42(-24.944,16.266) AK43(-25.897,16.266) AK45(-26.874,16.266) AK46(-27.776,16.266) AK48(-28.83,16.266) AK49(-29.732,16.266) AK51(-30.735,16.266) AK52(-31.583,16.266) AK54(-32.61,16.266) AK55(-33.562,16.266) AK57(-34.509,16.266) AK58(-35.408,16.266)
